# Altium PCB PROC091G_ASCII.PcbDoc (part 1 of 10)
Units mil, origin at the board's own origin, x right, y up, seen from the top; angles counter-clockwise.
Board outline 4538.11 x 994.94 mil, 8 copper layers (Top Layer, GND1, Sig1, PWR1, PWR2, Sig2, GND2, Bottom Layer), stack 59.155 mil thick; 447 components, 329 nets, 5050 pads, 868 vias.
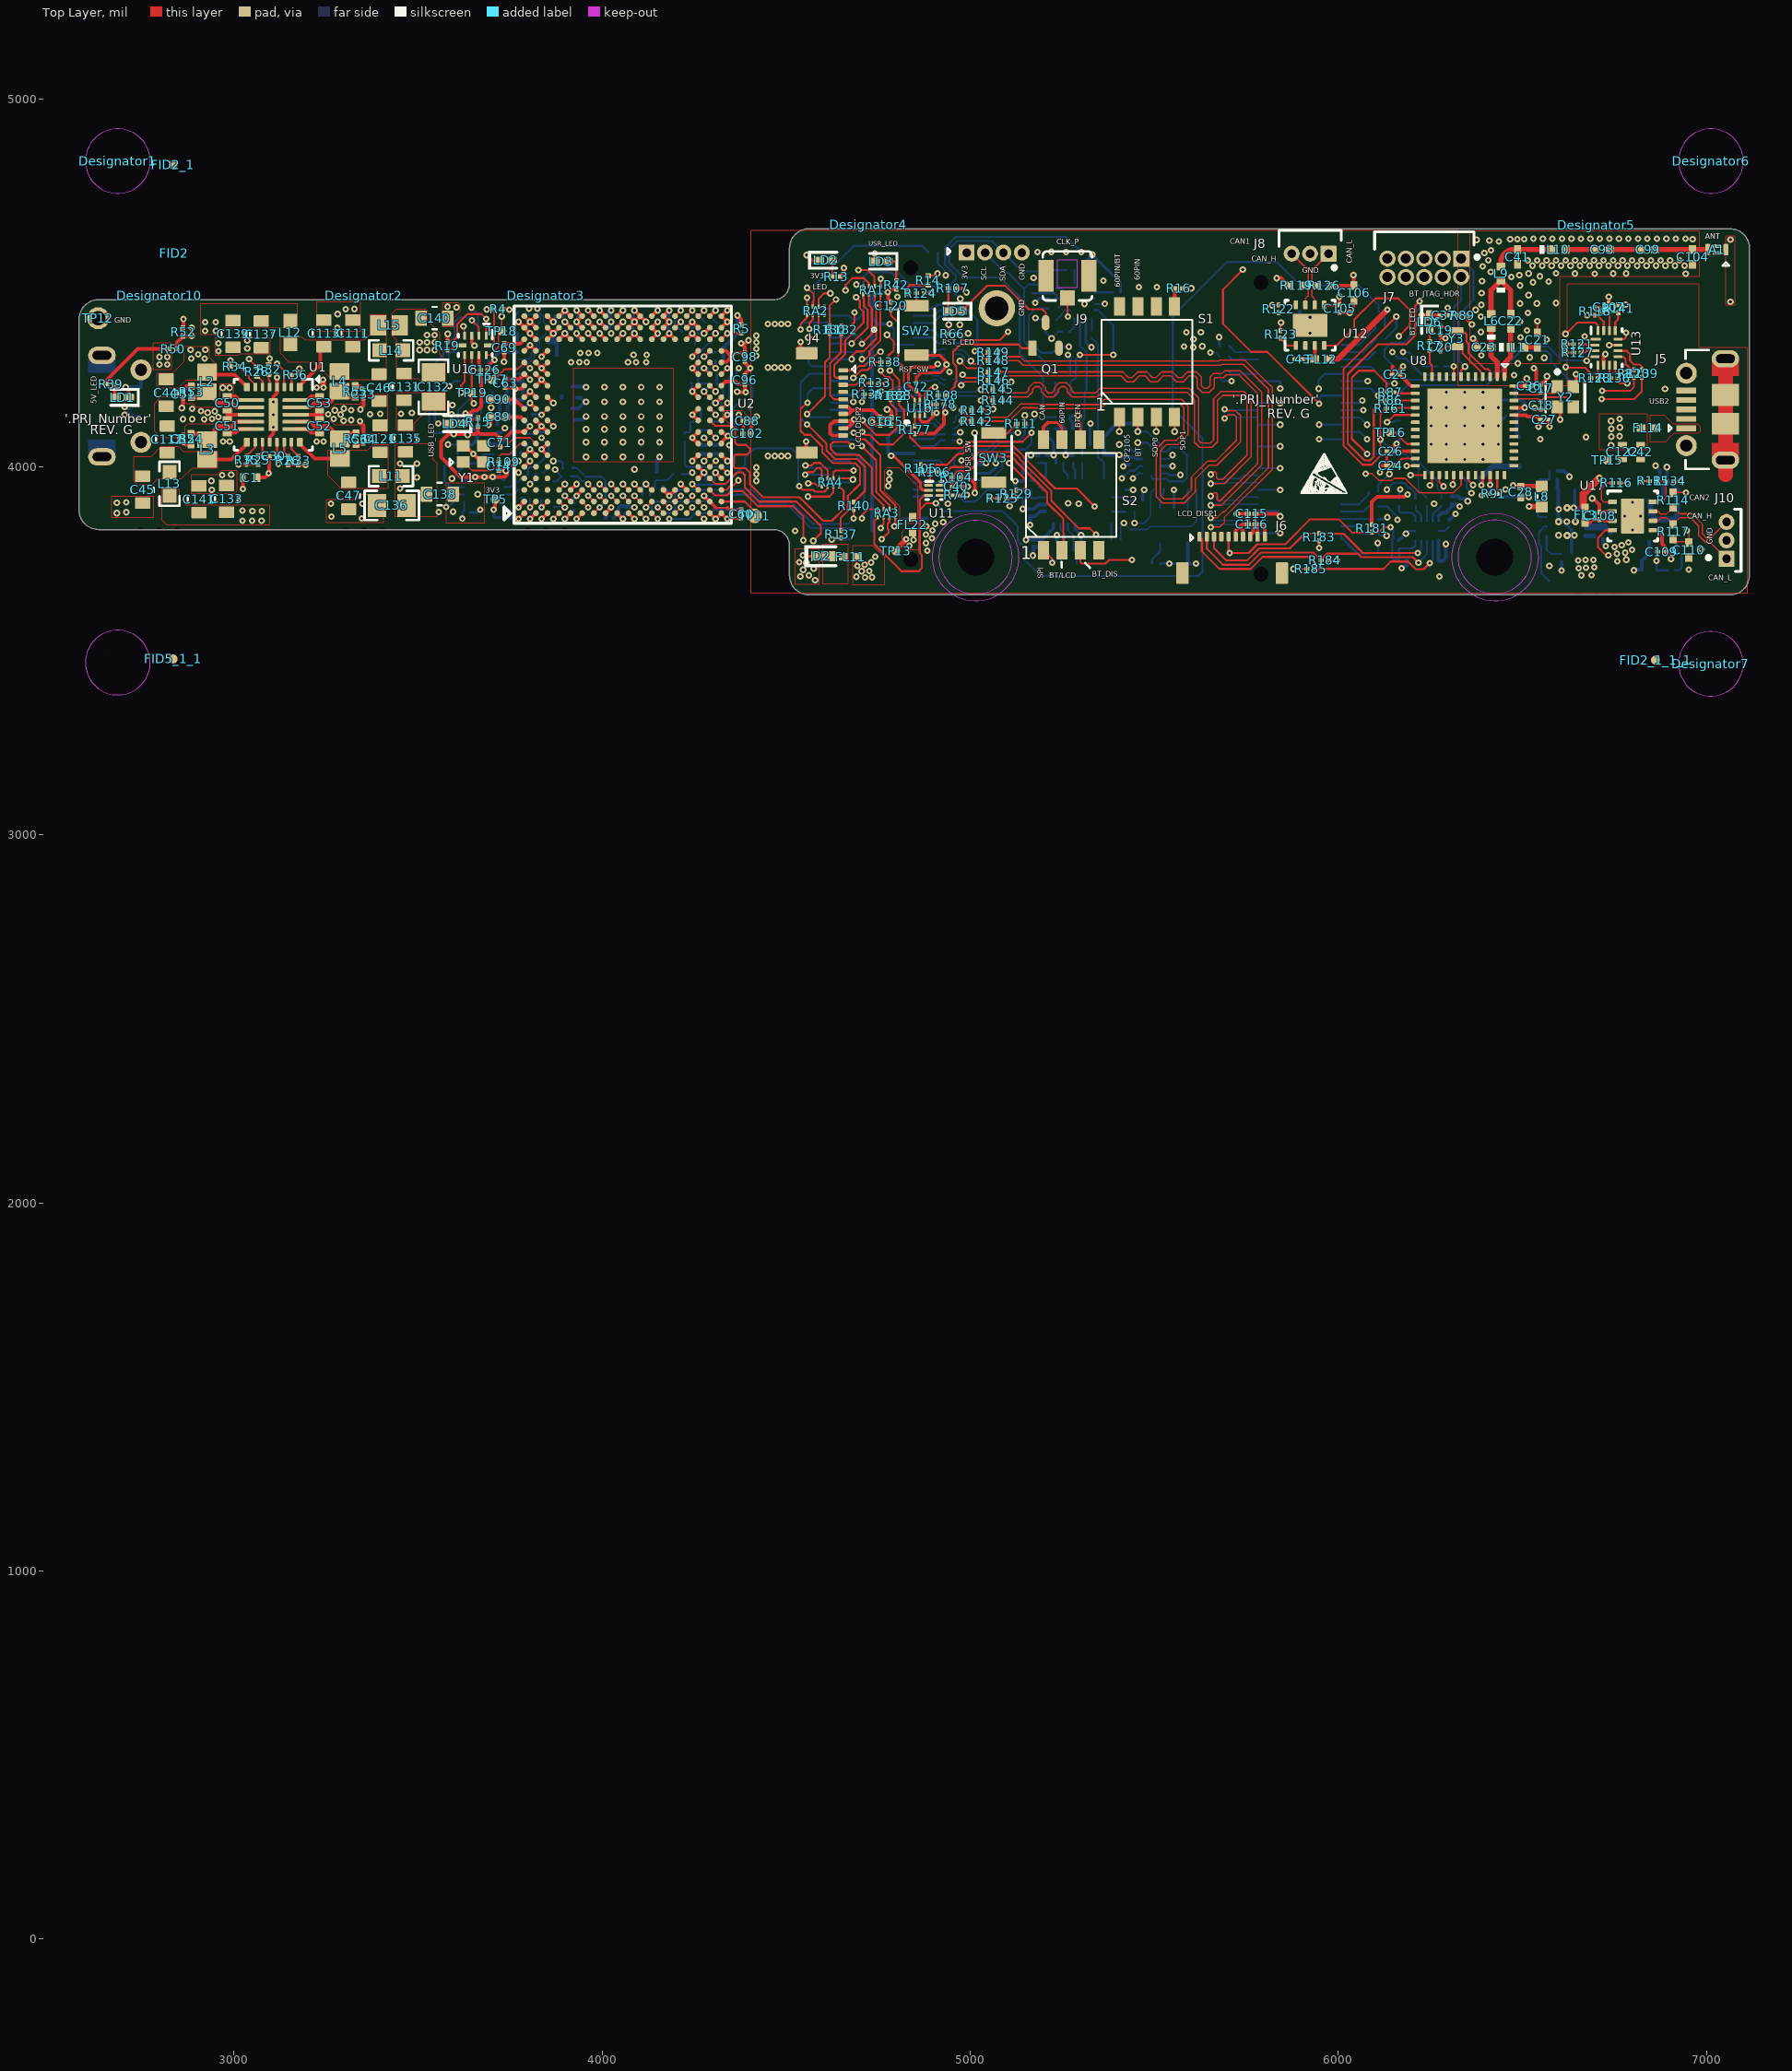
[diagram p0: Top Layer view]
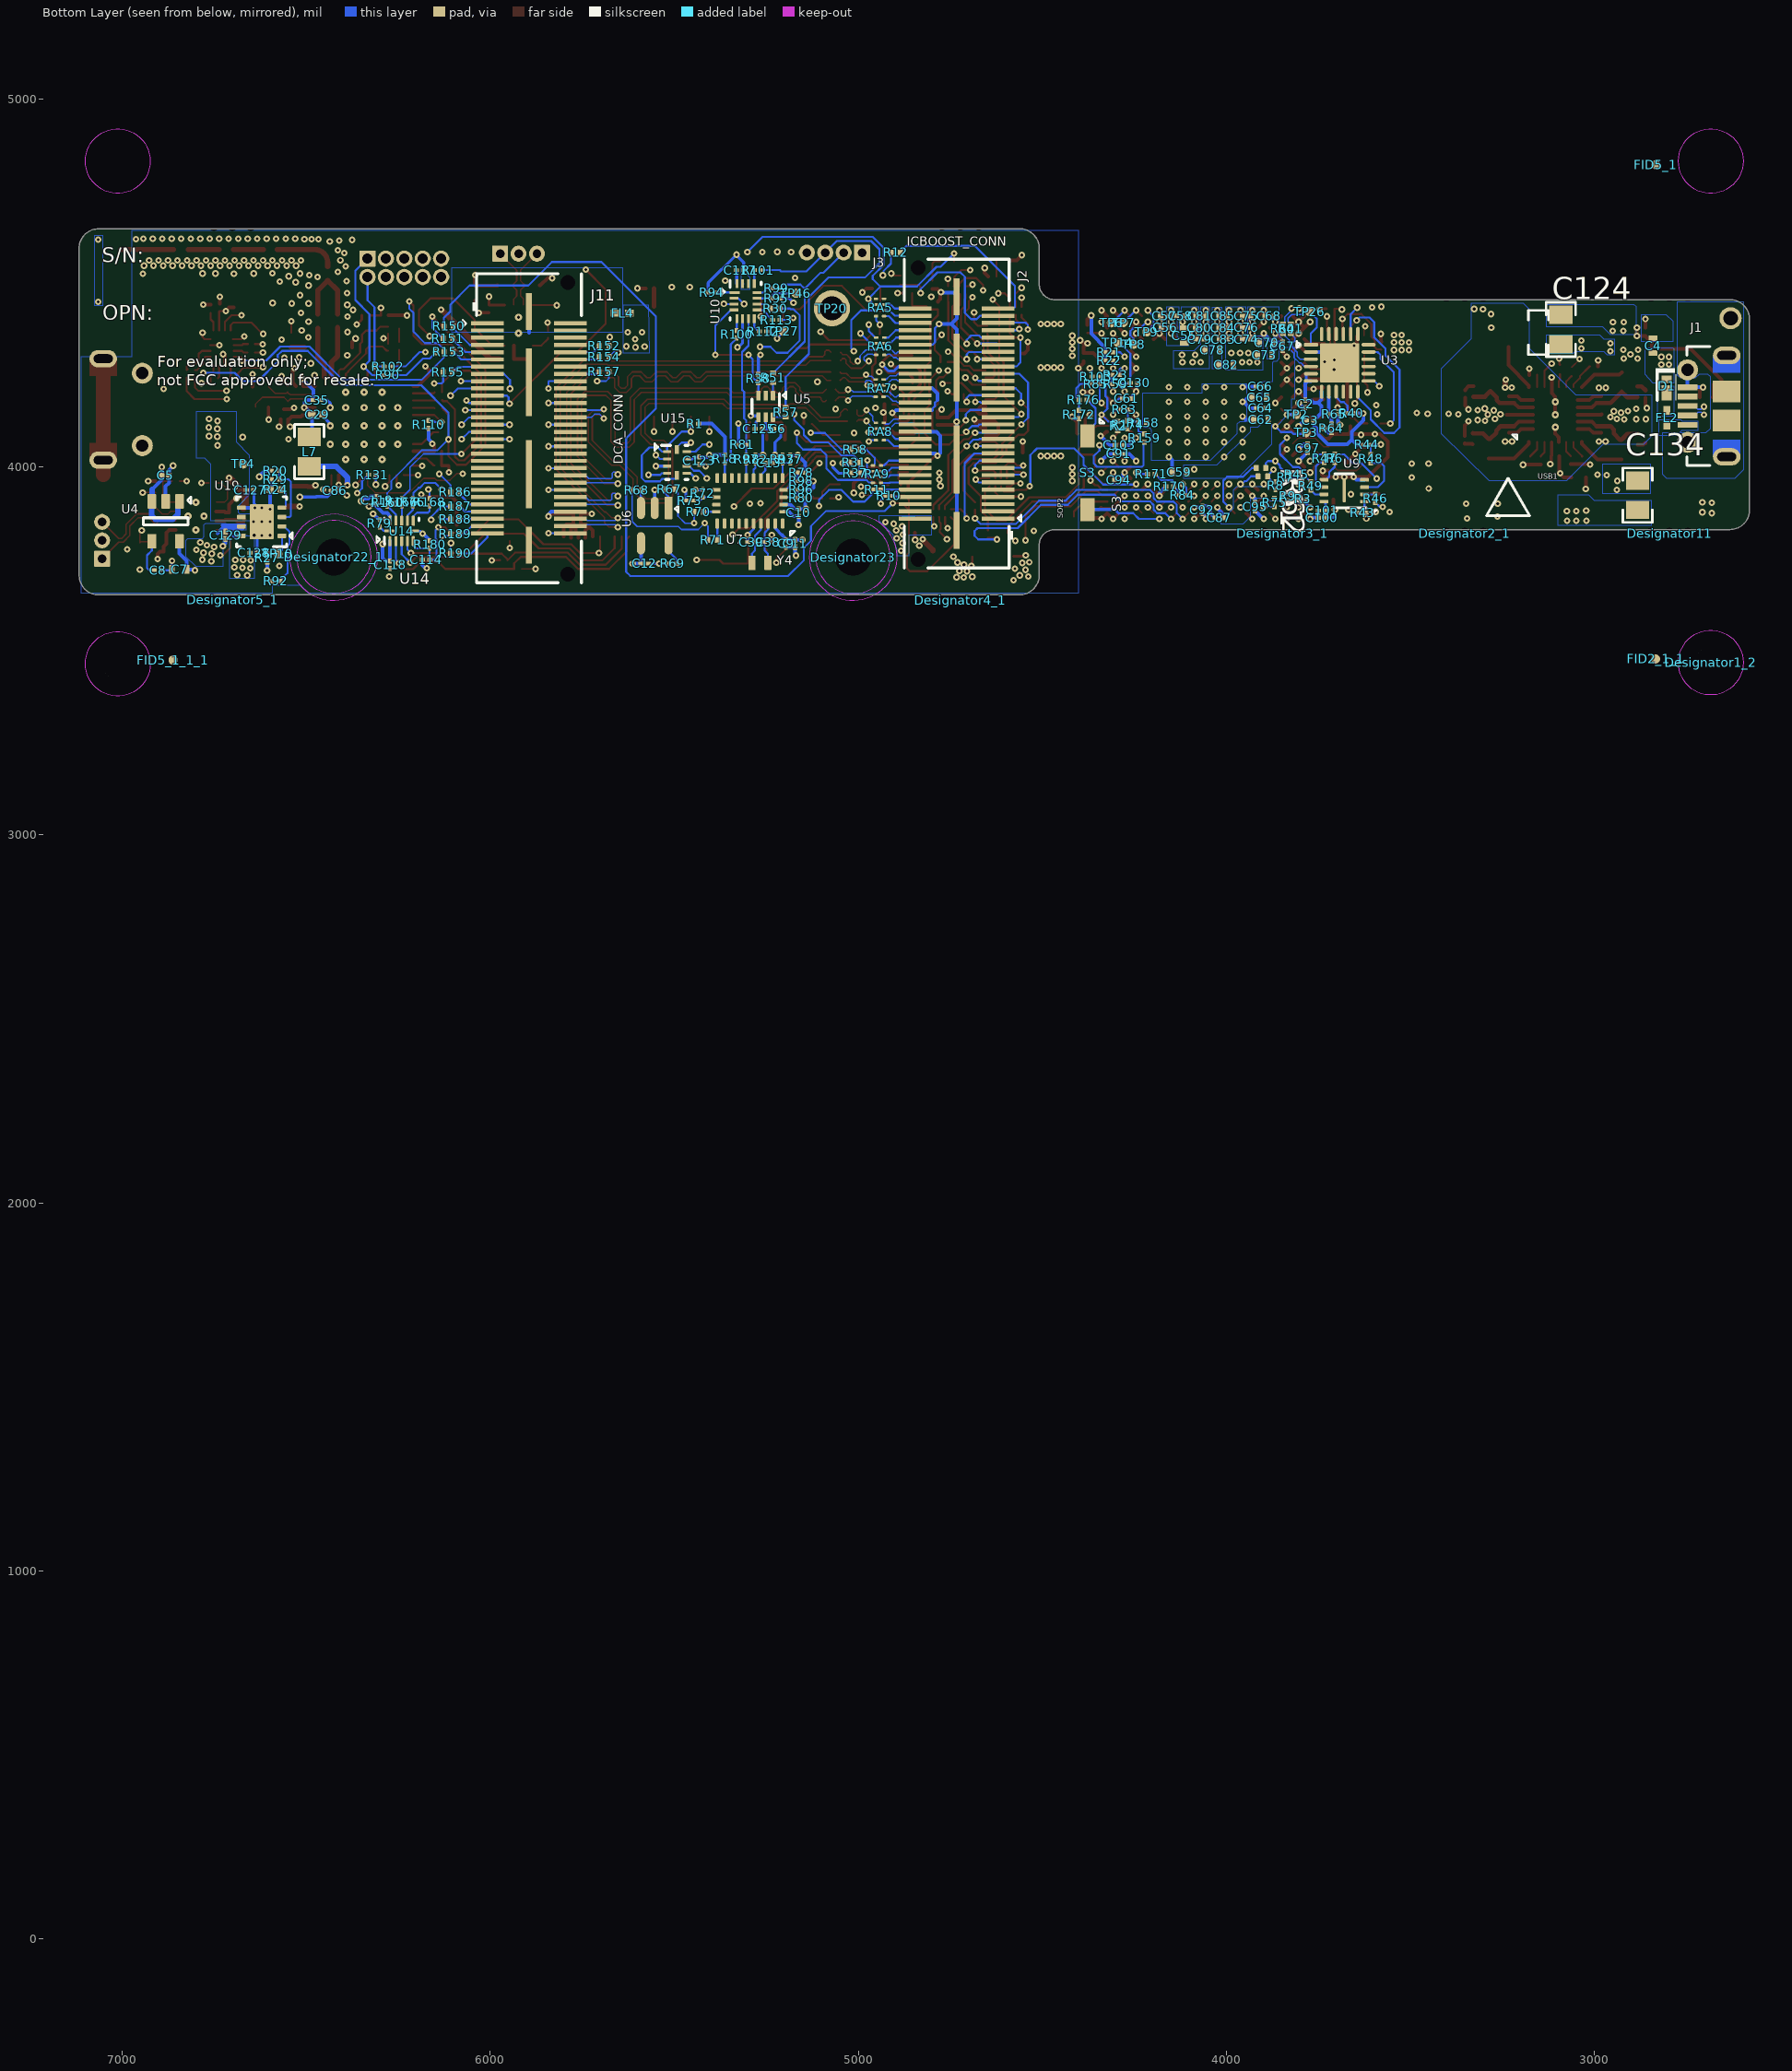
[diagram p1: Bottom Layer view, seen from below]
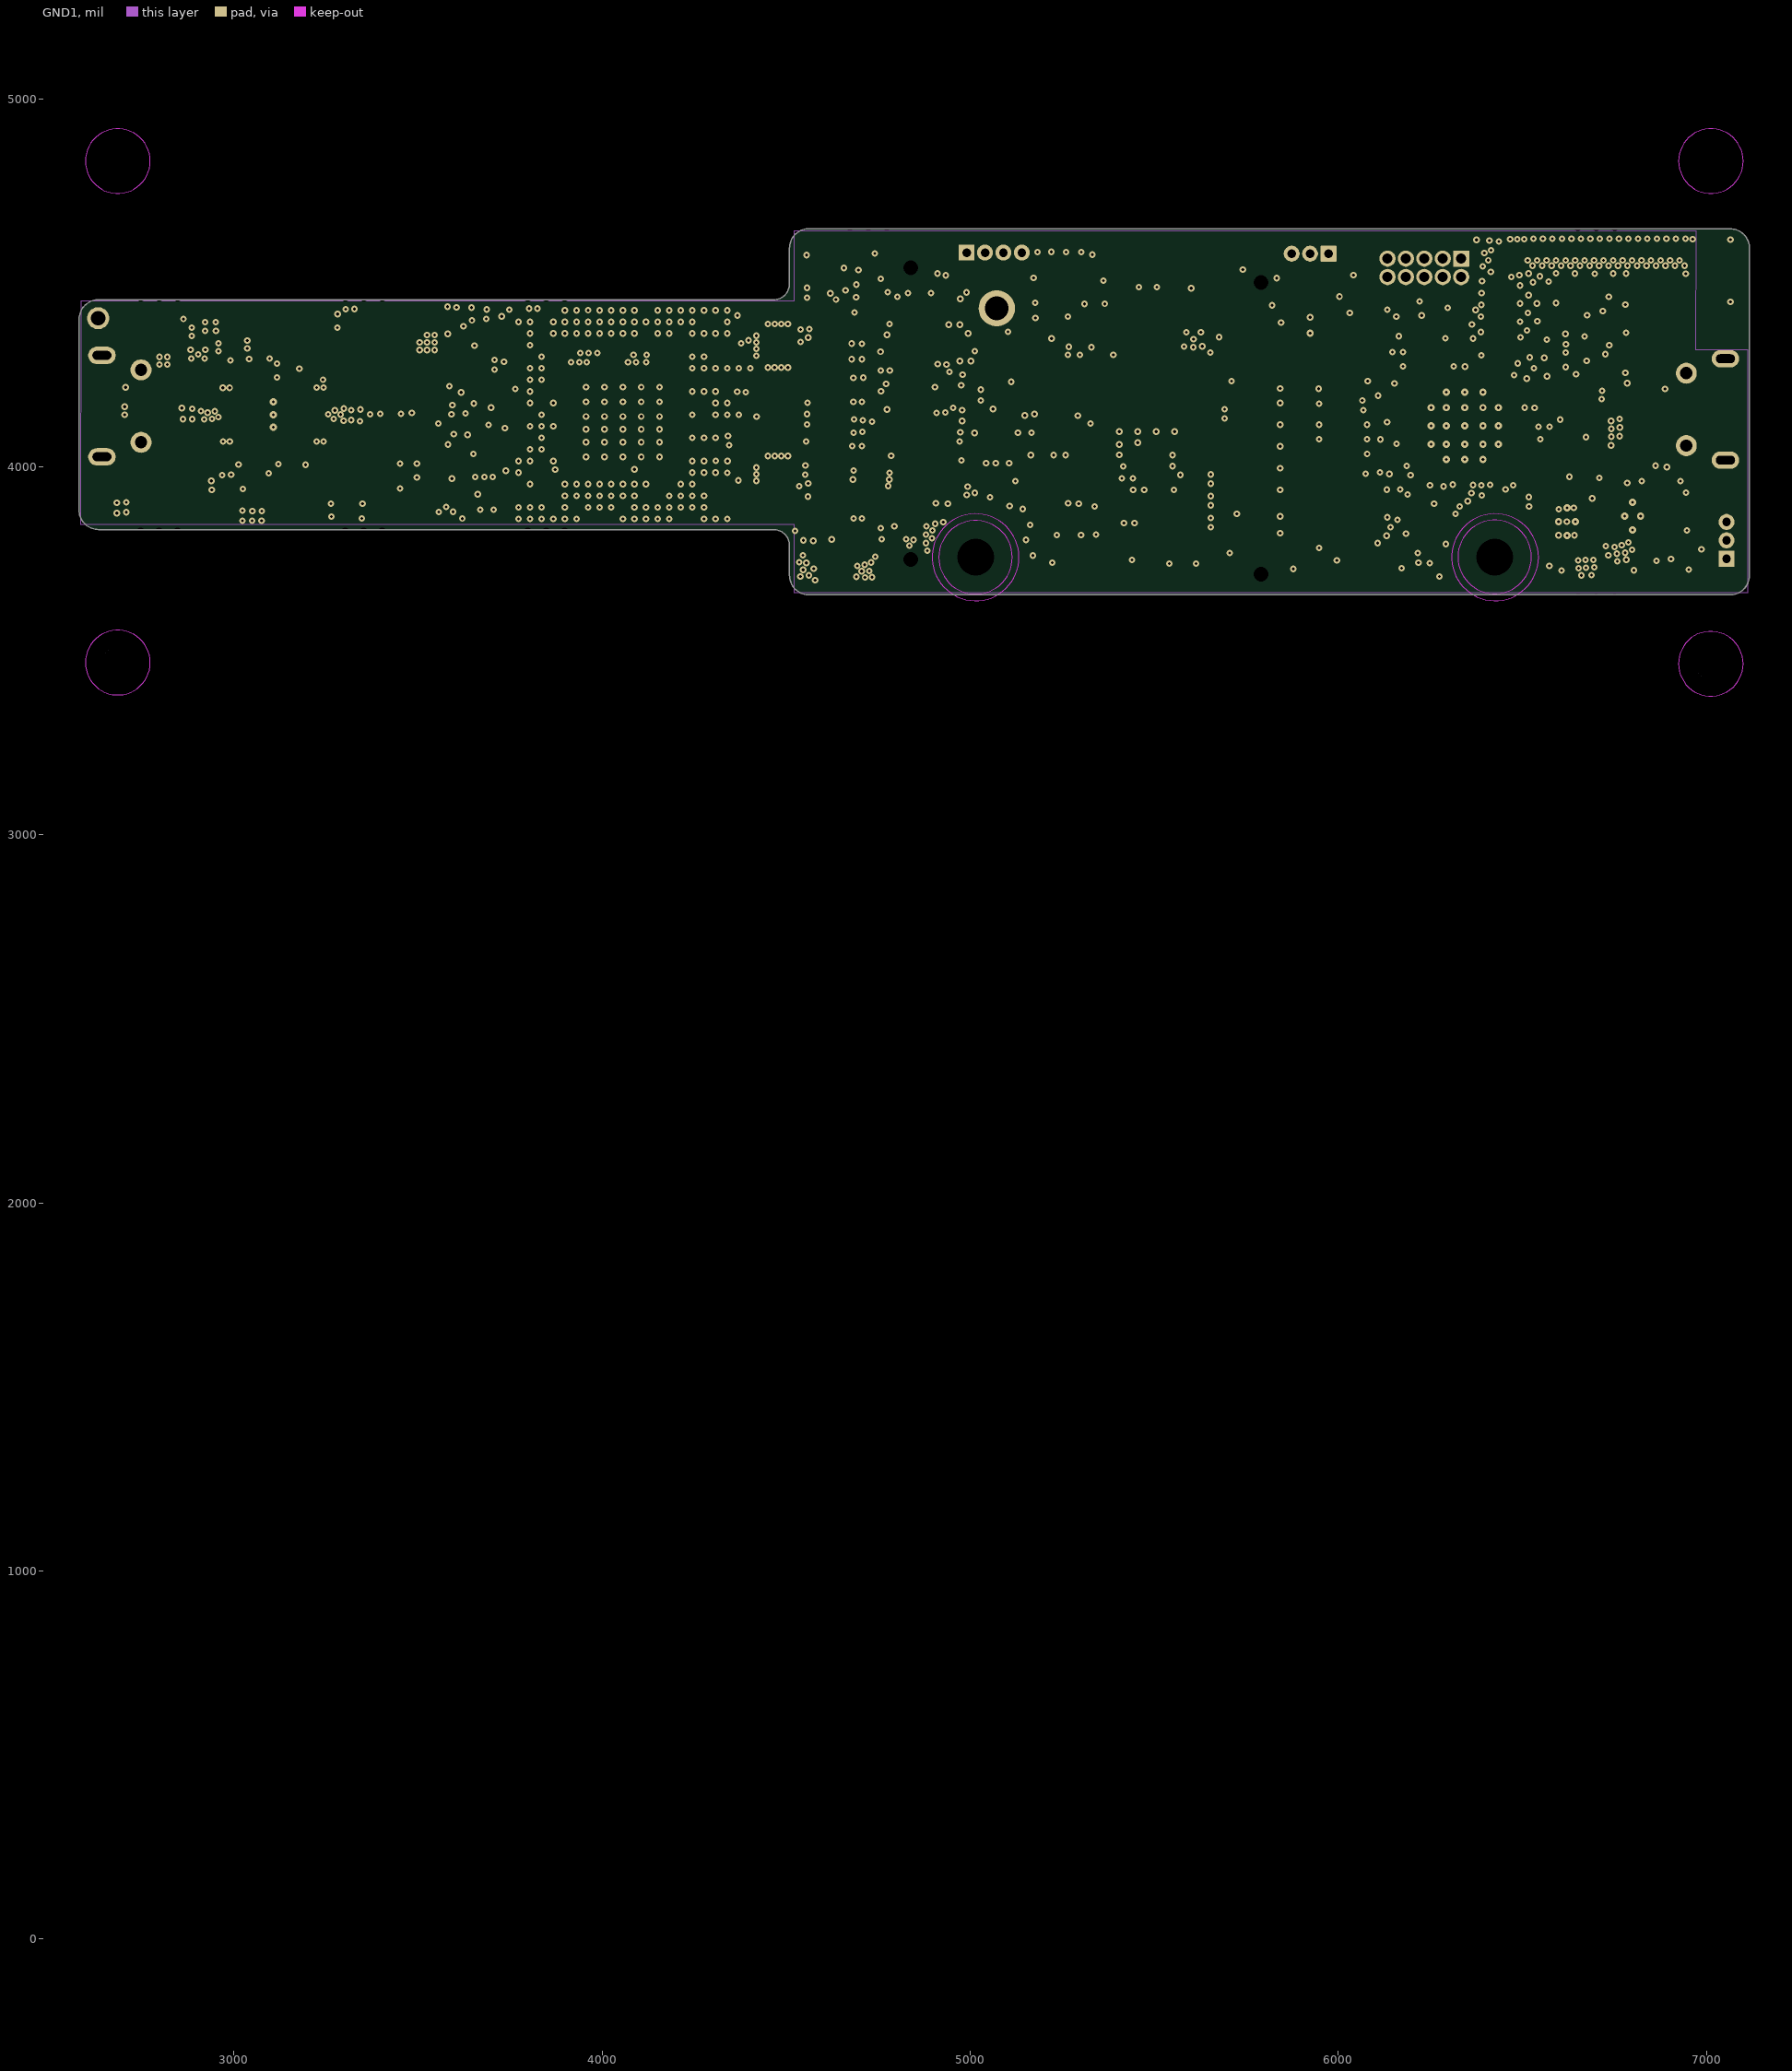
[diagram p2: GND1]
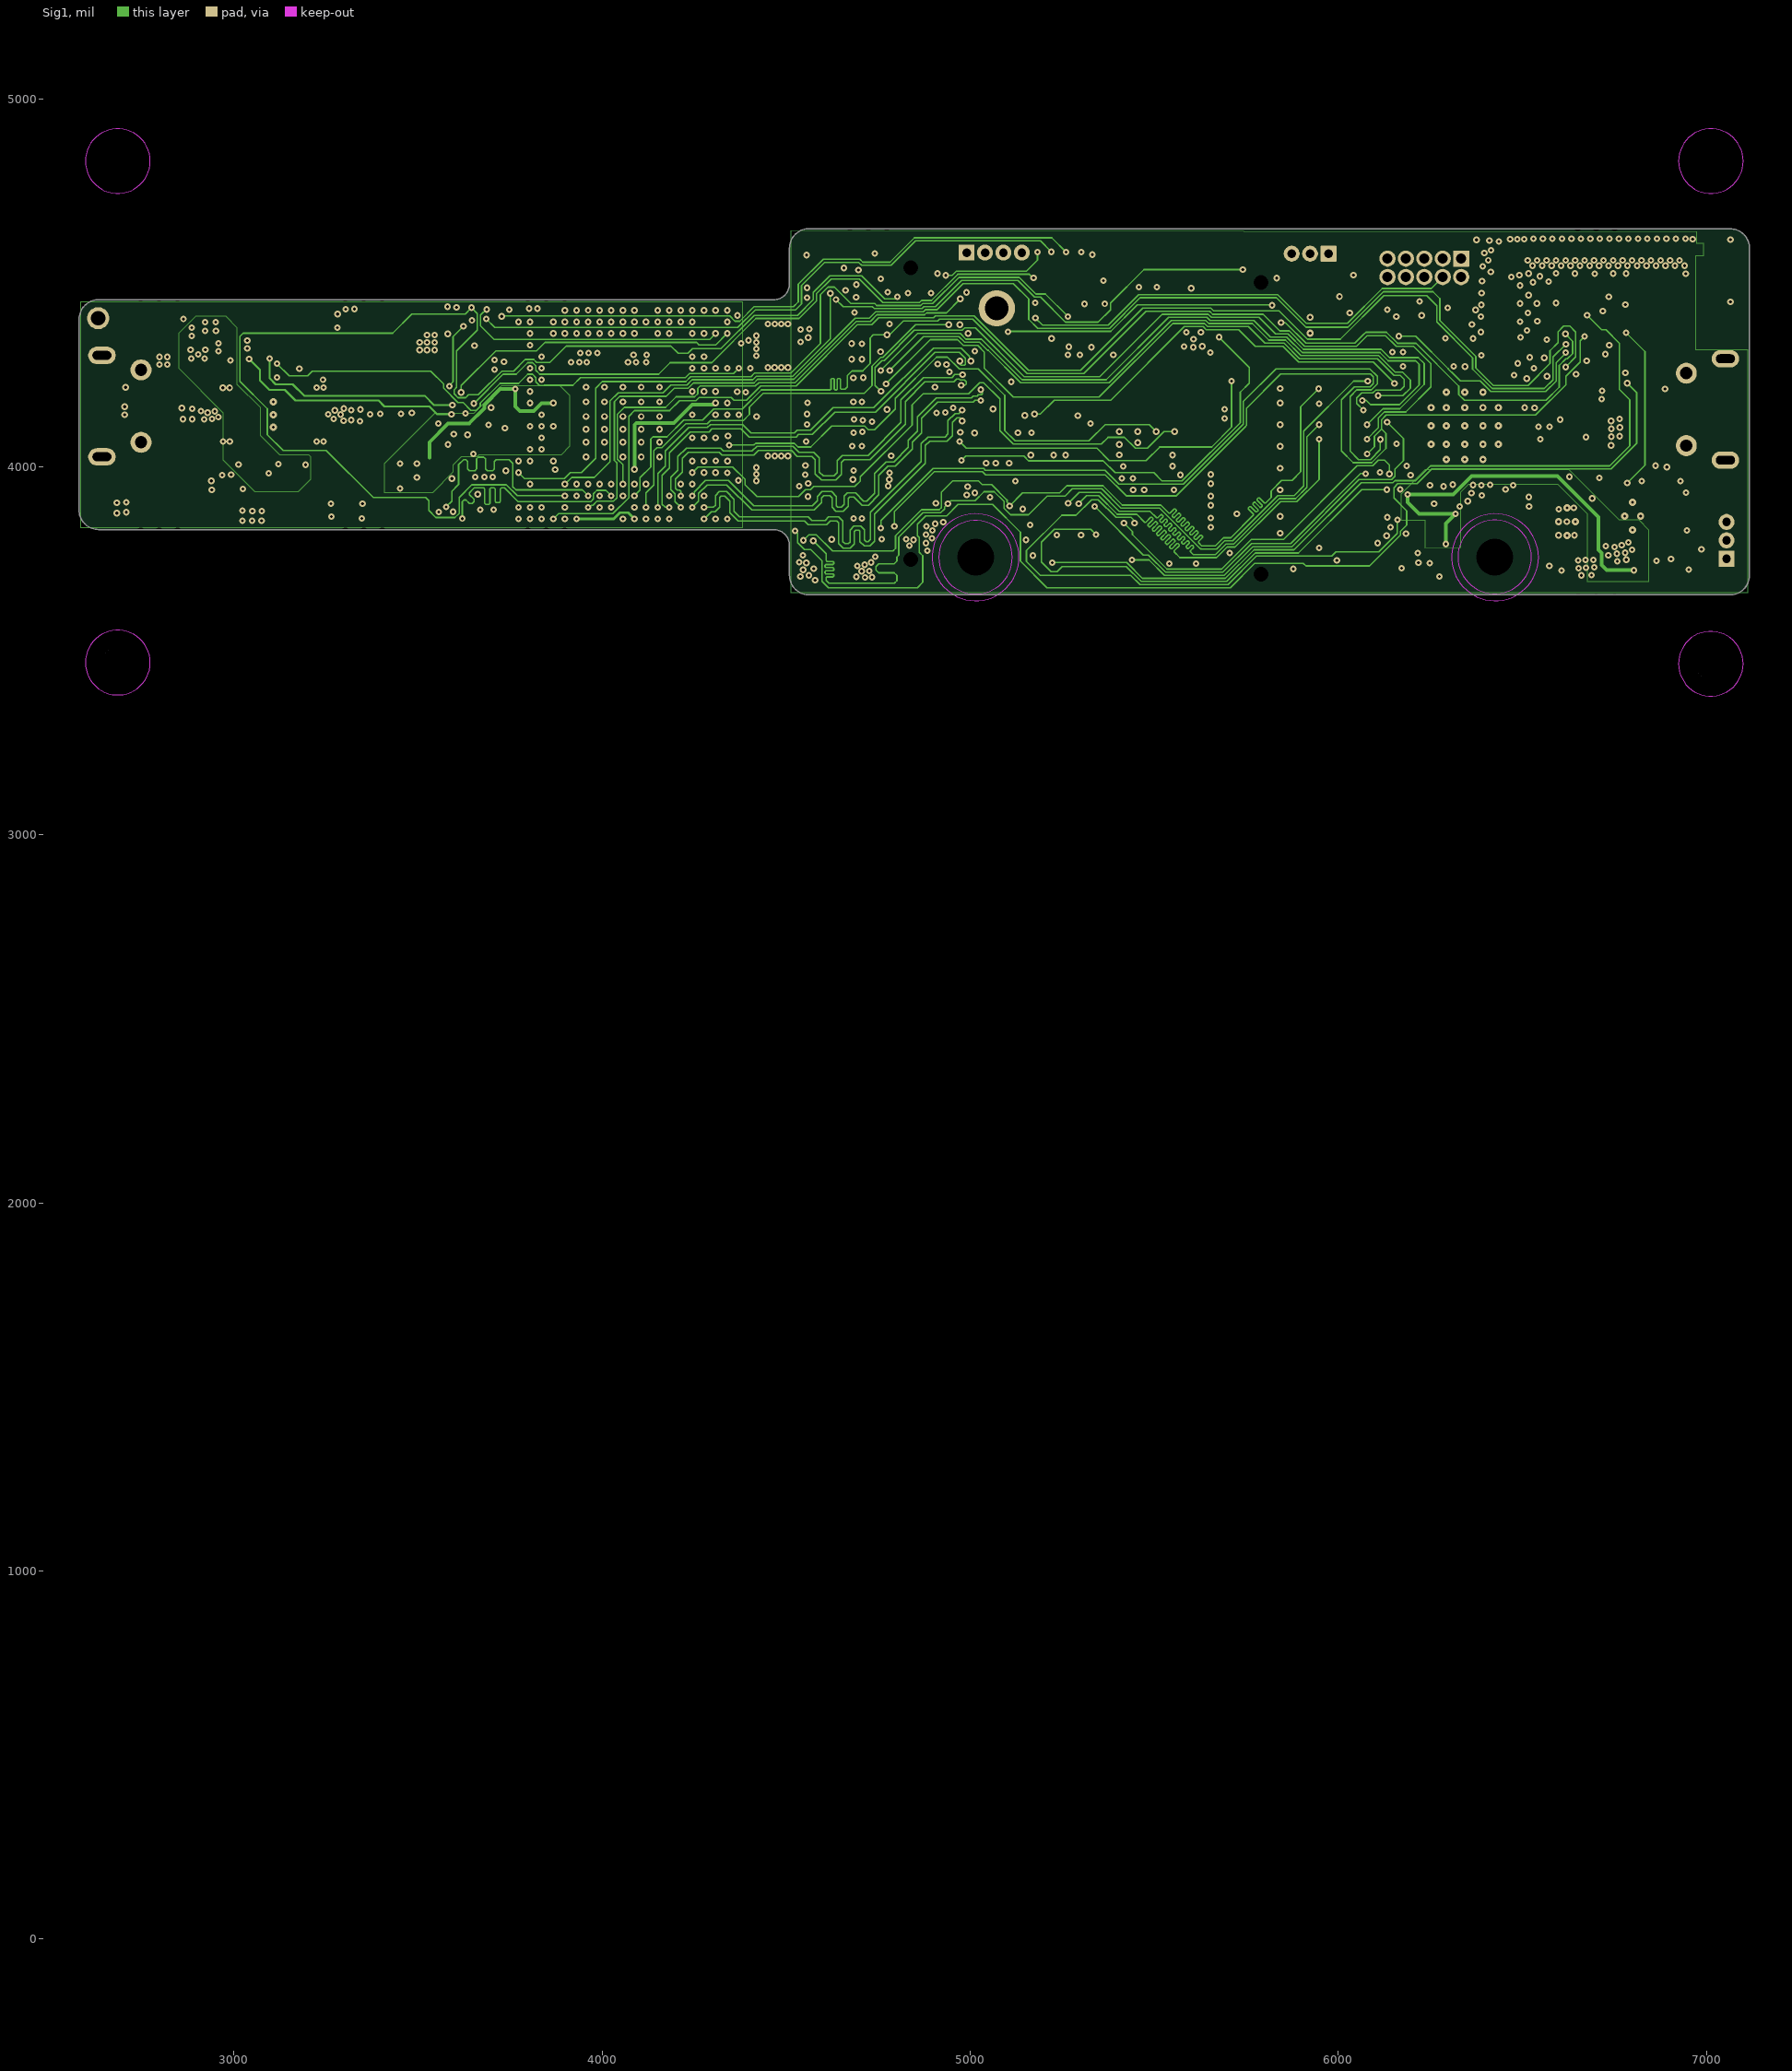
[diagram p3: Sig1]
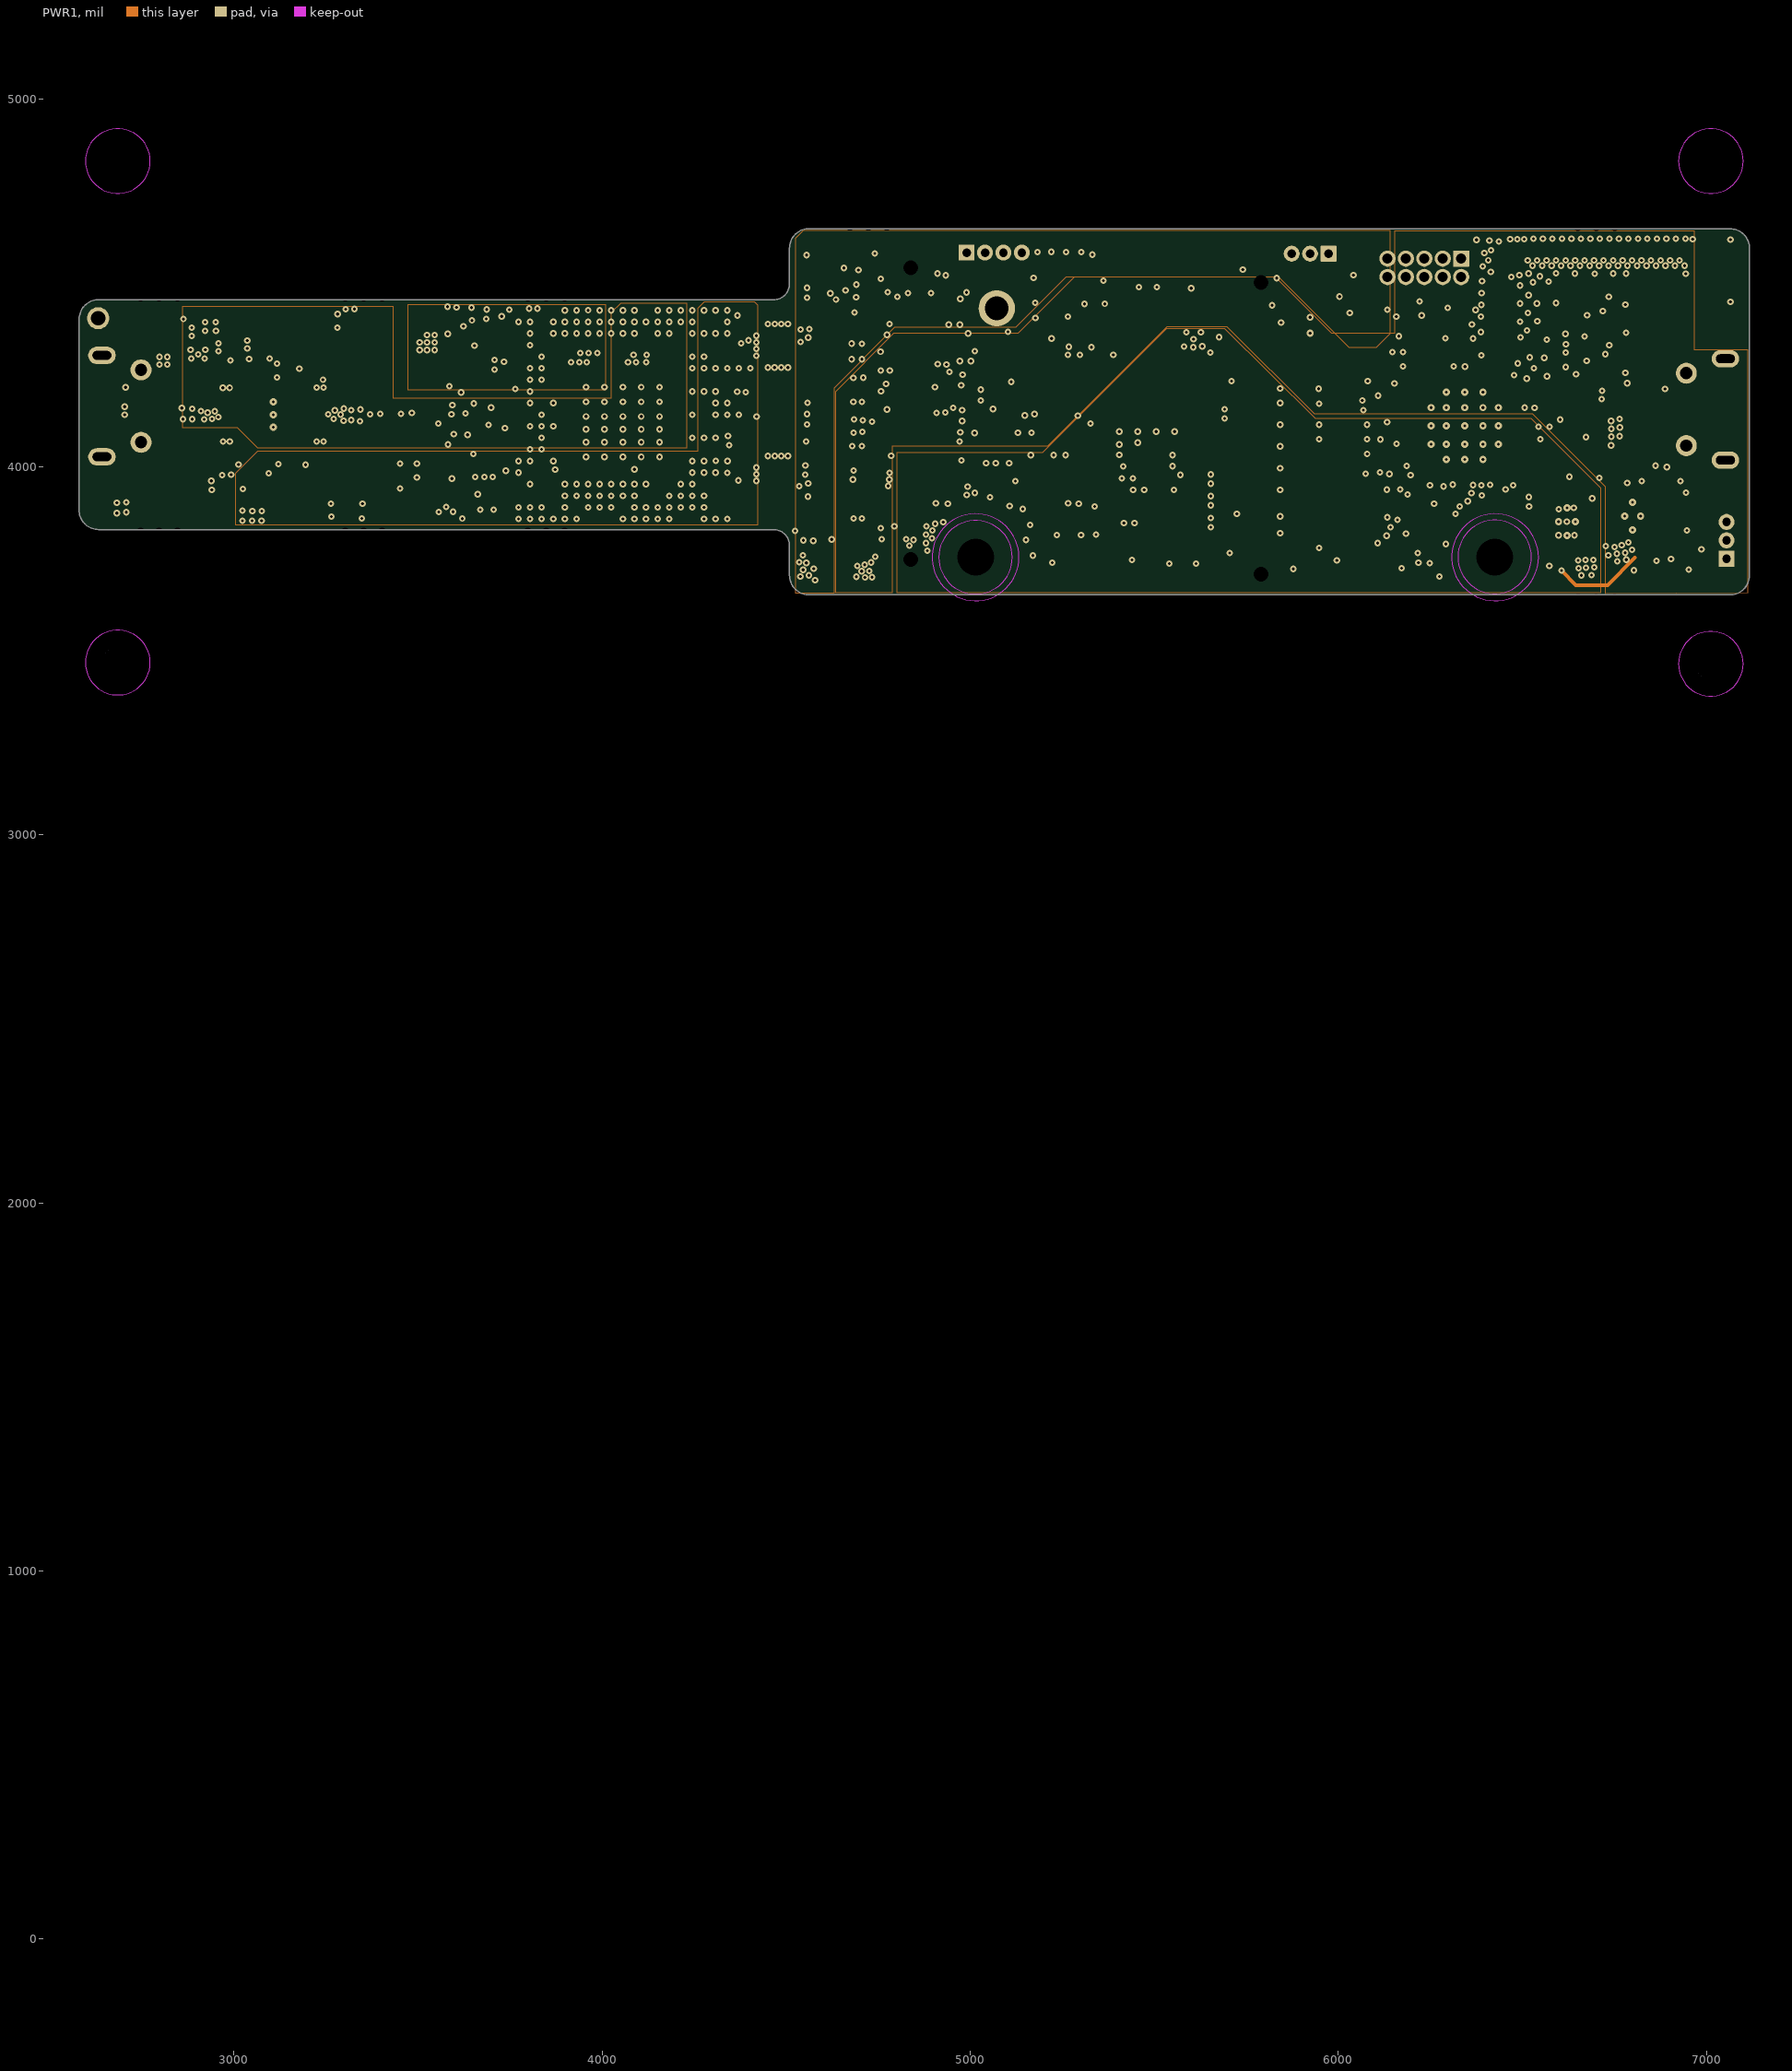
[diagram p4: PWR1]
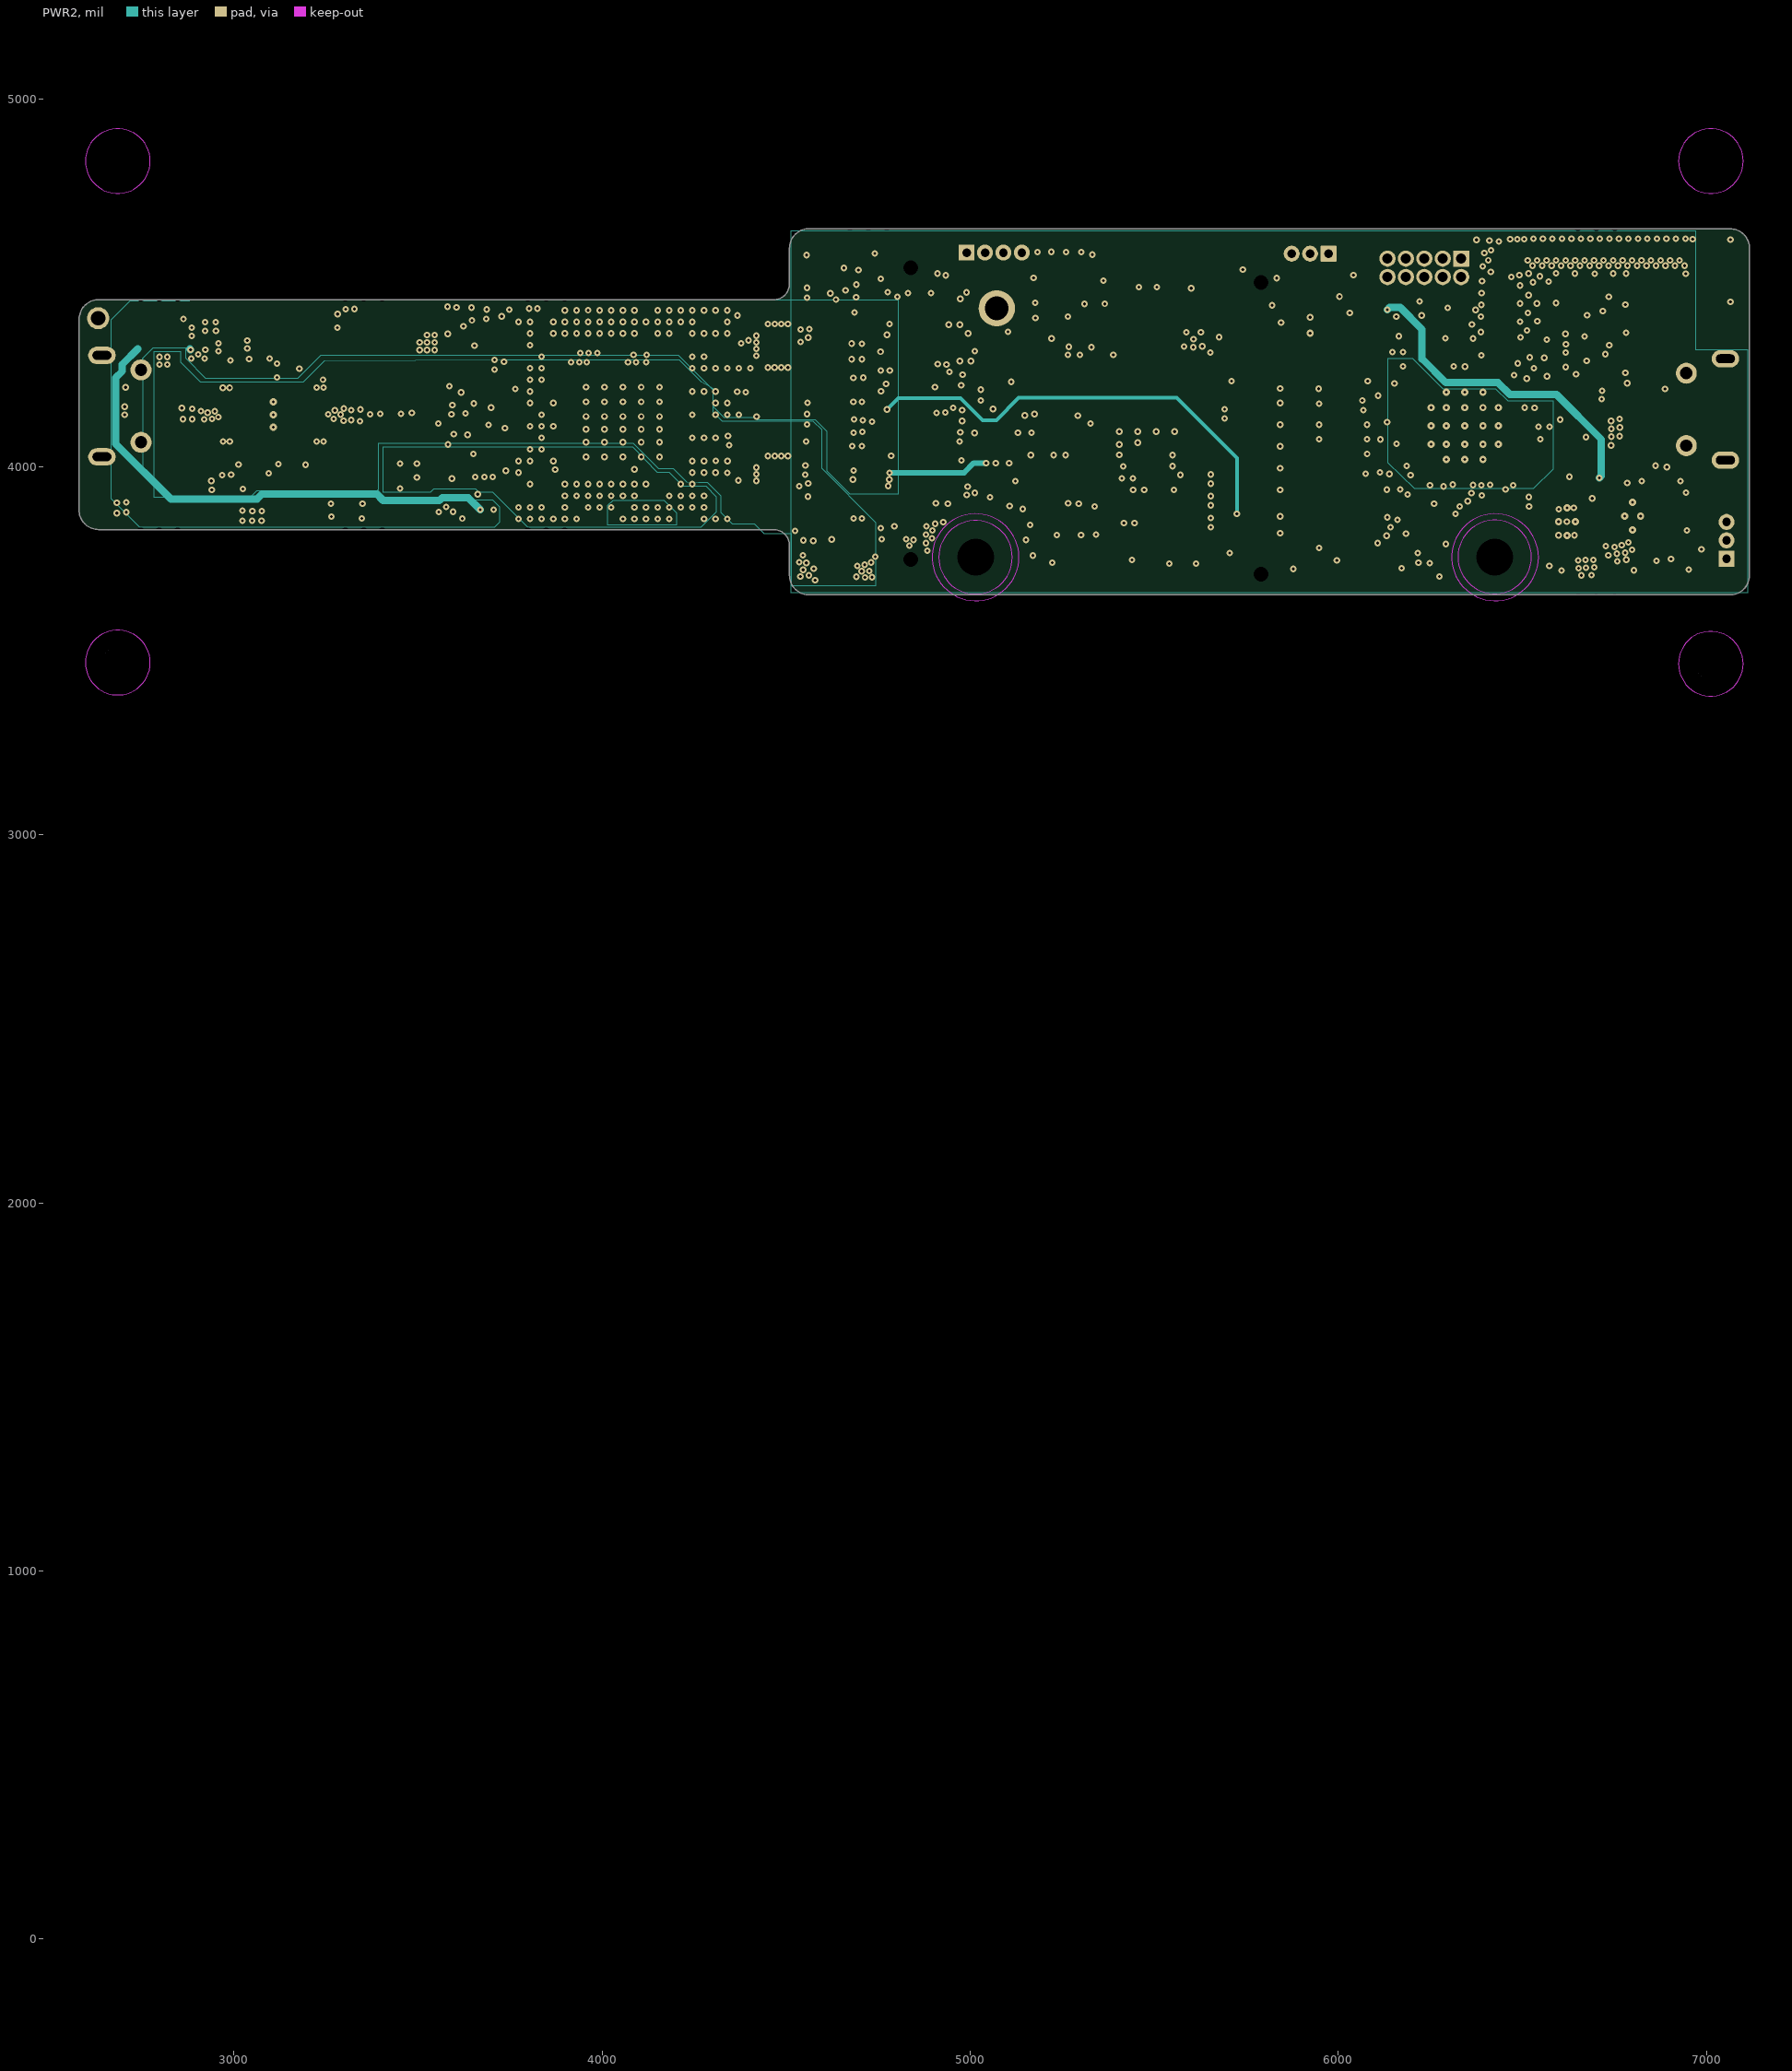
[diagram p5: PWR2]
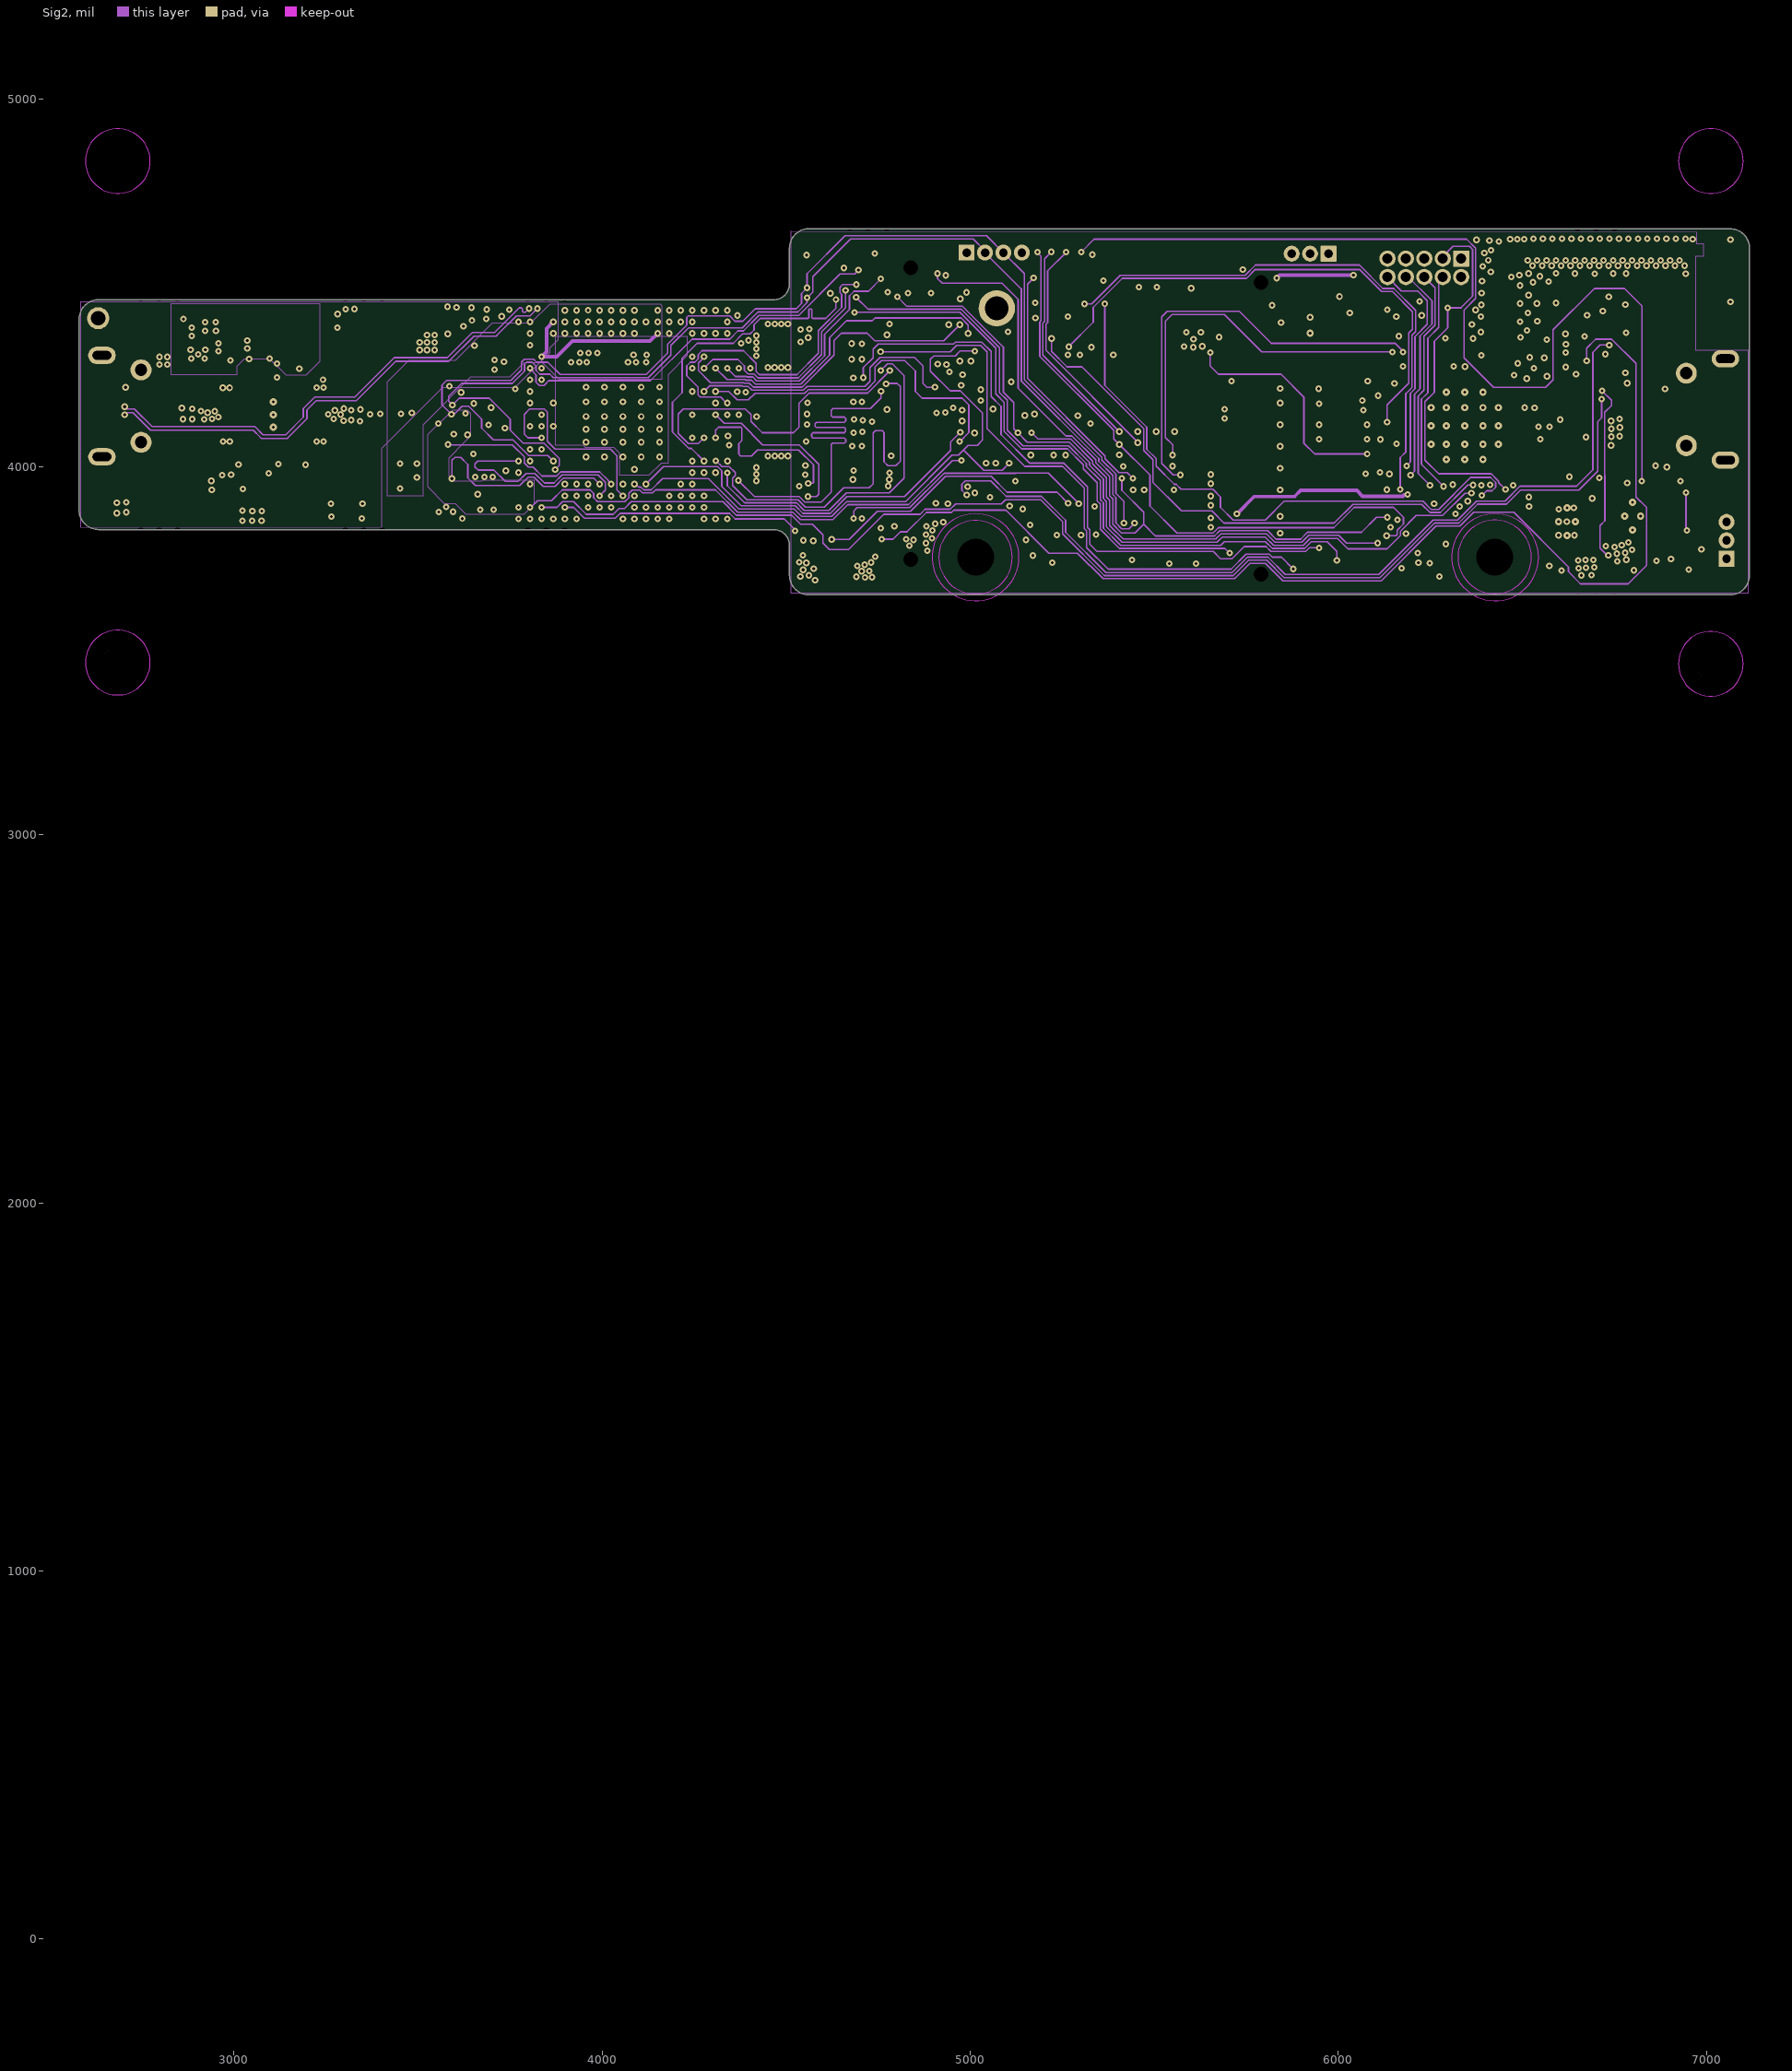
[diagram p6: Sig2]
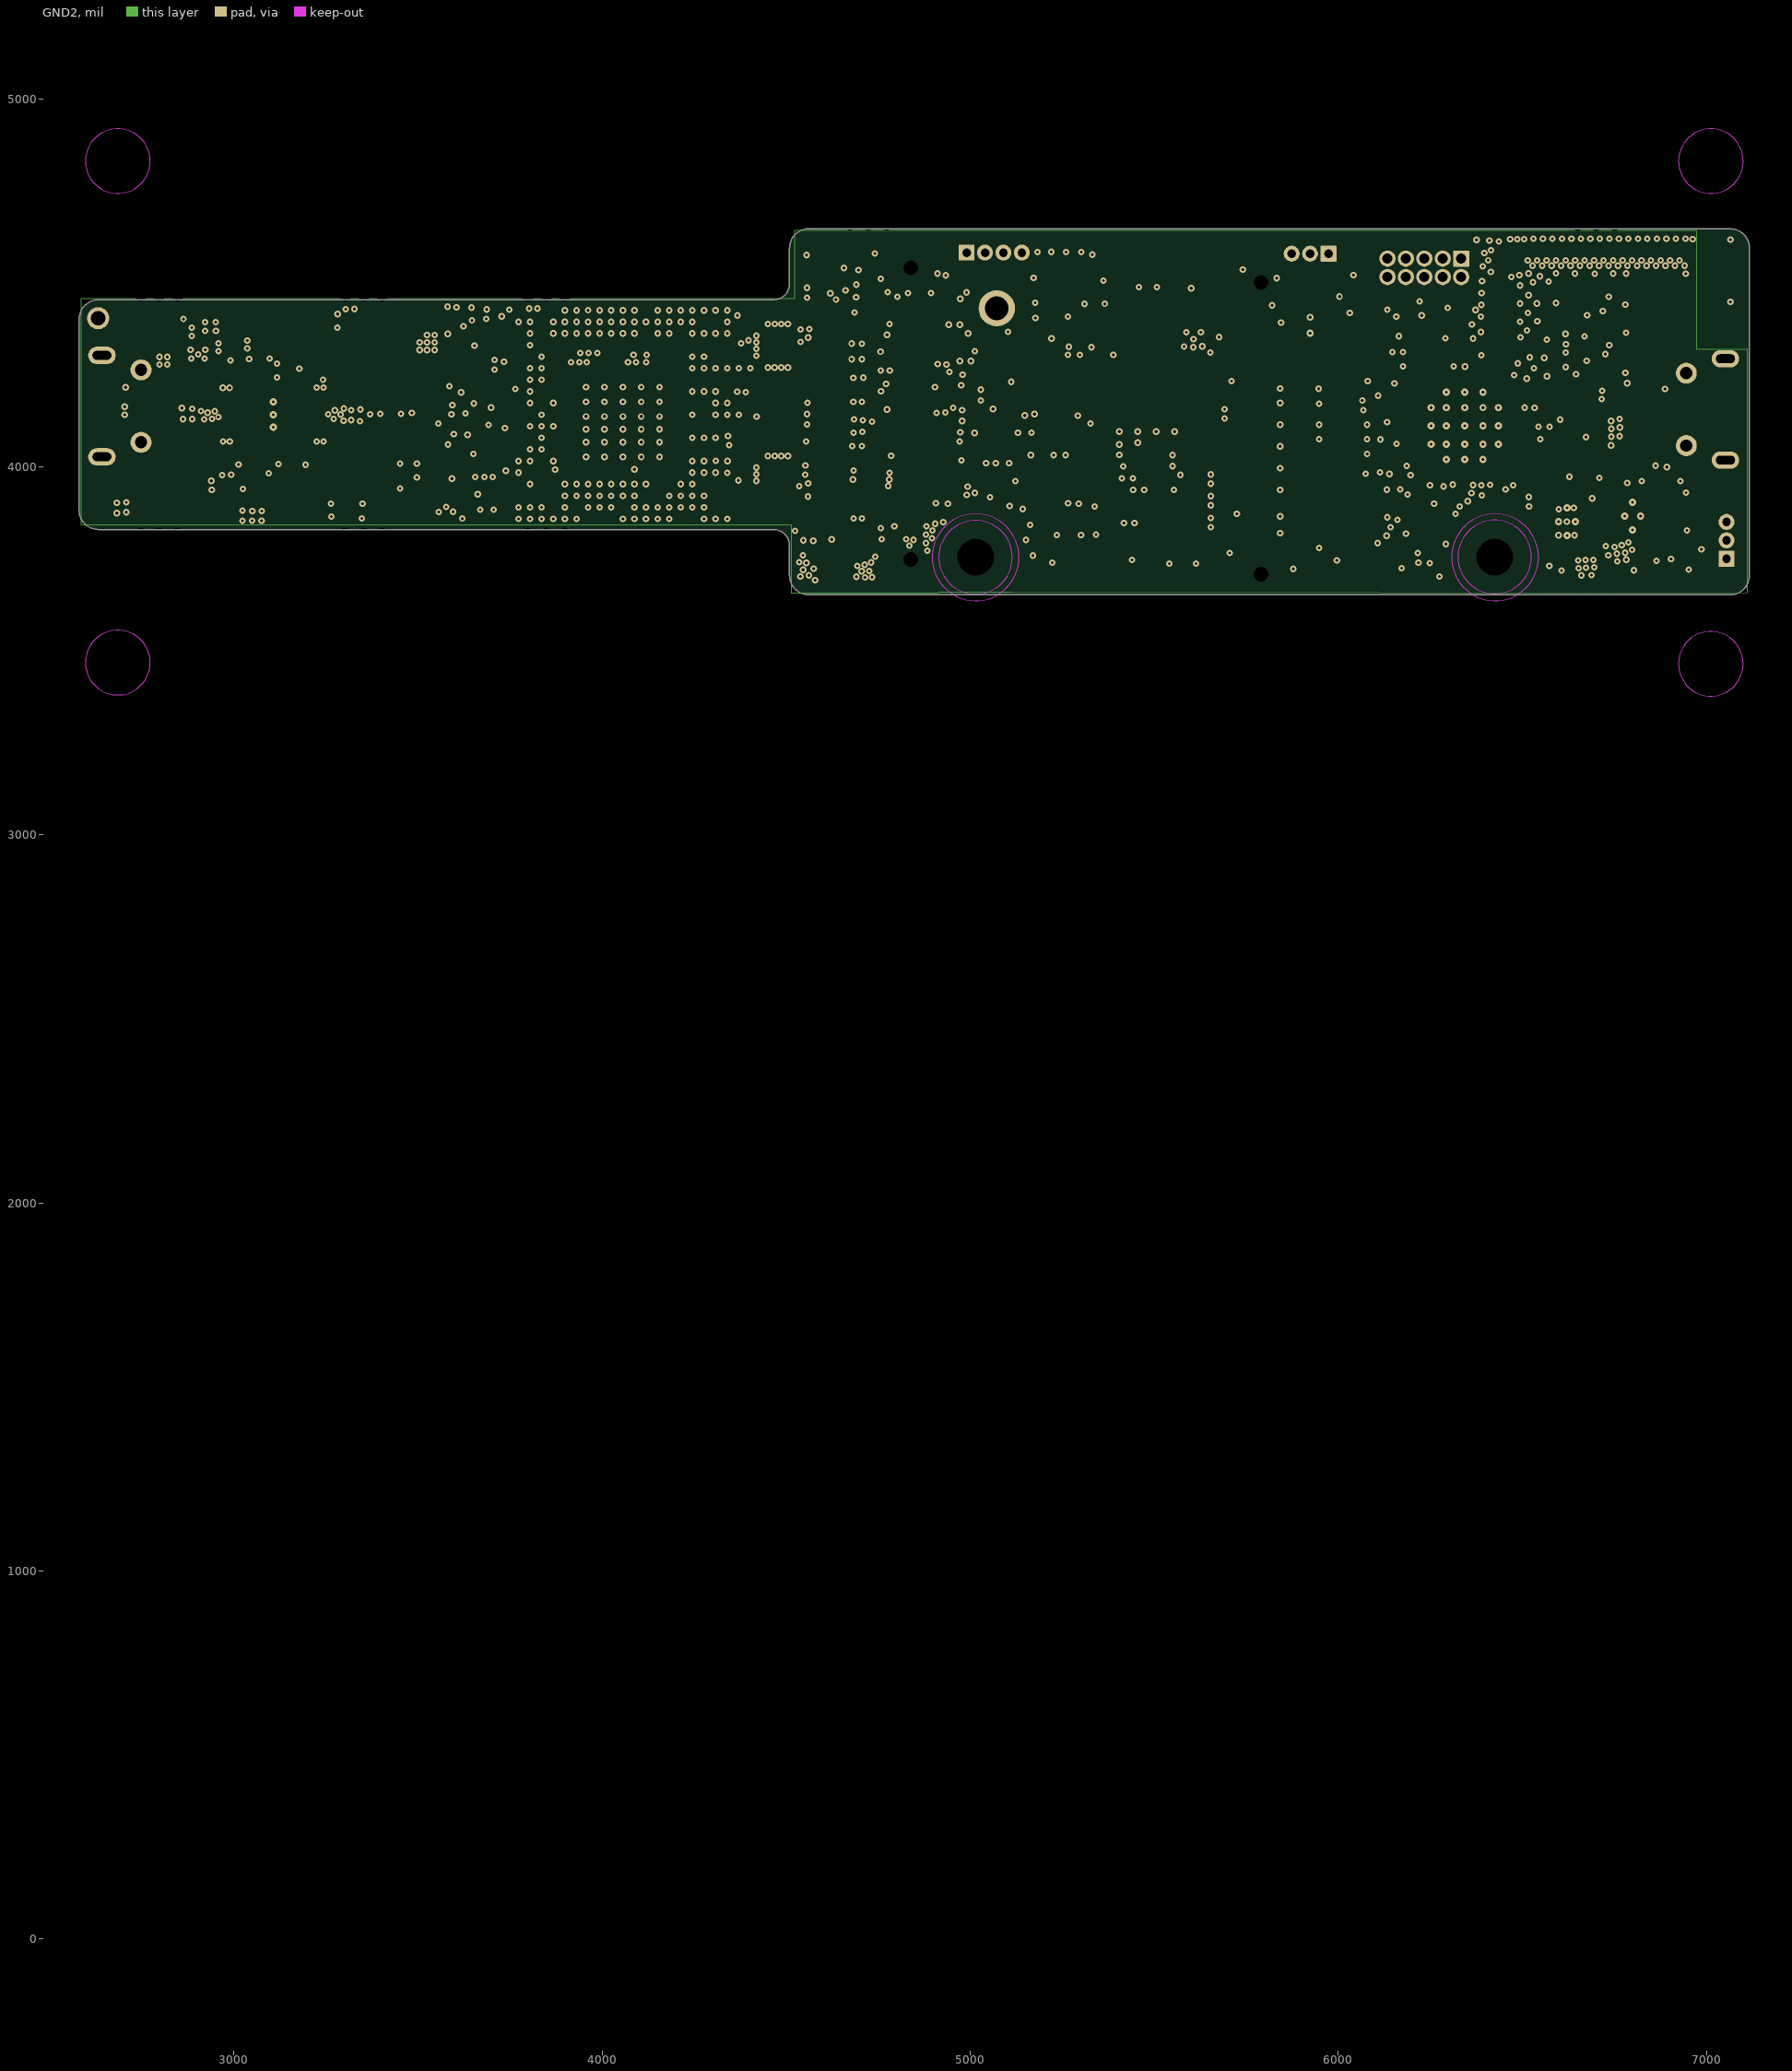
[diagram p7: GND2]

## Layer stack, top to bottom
Top Solder: solder mask 2, Solder Resist, Dk 4.4
Top Layer: signal copper 1.85
Dielectric1: core 1.462, FR-4 High Tg, Dk 3.79
Dielectric 2: dielectric 2.224, Dk 3.86
GND1: signal copper 2.638
Dielectric3: dielectric 4, FR-4 High Tg, Dk 4.4
Sig1: signal copper 1.26
Dielectric4: dielectric 3.162, FR-4 High Tg, Dk 4.13
Dielectric 5: dielectric 3.162, Dk 4.13
Dielectric 6: dielectric 3.162, Dk 4.13
PWR1: signal copper 2.638
Dielectric7: dielectric 8, FR-4 High Tg, Dk 4.41
PWR2: signal copper 2.638
Dielectric8: dielectric 3.175, FR-4 High Tg, Dk 4.13
Dielectric 9: dielectric 3.175, Dk 4.13
Dielectric 10: dielectric 3.175, Dk 4.13
Sig2: signal copper 1.26
Dielectric11: dielectric 4, FR-4 High Tg, Dk 4.4
GND2: signal copper 2.638
Dielectric12: dielectric 2.224, FR-4 High Tg, Dk 3.86
Dielectric 13: dielectric 1.462, Dk 3.79
Bottom Layer: signal copper 1.85
Bottom Solder: solder mask 2, Solder Resist, Dk 4.4

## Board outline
2632.27,3829.45 2632.34,3829.45 4466.14,3829.45 cw(c4466.14,3786.46) 4509.12,3786.46 4509.12,3705.09 ccw(c4562.14,3705.09) 4562.14,3652.08 ccw(c4562.14,3657.09) 4562.83,3652.13 7062.33,3652.13 ccw(c7064.08,3656.83) 7064.08,3651.81 ccw(c7064.08,3704.83) 7117.07,3703.16 ccw(c7112.34,3704.83) 7117.35,3704.83 7117.35,4593.25 ccw(c7112.34,4593.47) 7117.36,4593.47 ccw(c7064.34,4593.47) 7064.34,4646.49 ccw(c7064.34,4641.47) 7063.39,4646.4 4562.79,4646.71 ccw(c4562.15,4641.74) 4562.15,4646.75 ccw(c4562.15,4593.74) 4509.14,4593.74 4509.14,4496.76 4509.13,4496.76 cw(c4514.15,4496.76) 4509.14,4496.84 4509.13,4496.76 cw(c4466.15,4496.76) 4466.15,4453.77 2634.33,4453.77 ccw(c2632.58,4449.07) 2632.58,4454.09 ccw(c2632.58,4401.07) 2579.56,4401.07 ccw(c2584.58,4401.07) 2579.57,4400.91 ccw(c2584.58,4400.76) 2579.56,4400.76 2579.56,3884.21 ccw(c2584.27,3882.46) 2579.25,3882.46 ccw(c2632.27,3882.46)

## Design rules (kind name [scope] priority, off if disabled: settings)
AcuteAngle [All] p0: scope1count=1 scope1_0_kind=Board scope1_0_value=Board scope2count=1 scope2_0_kind=Board scope2_0_value=Board commentlength=0 minimum=4.50000000000000E+0001
AcuteAngle [All] p1: minimum=4.50000000000000E+0001 checktracksonly=TRUE
AssemblyTestPointUsage [All] p0: scope1count=1 scope1_0_kind=Board scope1_0_value=Board scope2count=1 scope2_0_kind=Board scope2_0_value=Board commentlength=0
AssemblyTestPointUsage [All] p1: valid=2
AssemblyTestpoint [All] p0: scope1count=1 scope1_0_kind=Board scope1_0_value=Board scope2count=1 scope2_0_kind=Board scope2_0_value=Board commentlength=0
BoardOutlineClearance [All] p0 off: scope1count=1 scope1_0_kind=Board scope1_0_value=Board scope2count=1 scope2_0_kind=Board scope2_0_value=Board commentlength=133 gap=12 // Protel DXP Scope 1 Expression Was: All and (Not (OnLayer('Bottom Overlay') or OnLayer('Top Overlay') or InComponentClass('Fid')))
BoardOutlineClearance BoardOutlineClearance_1 [All] p0: scope1count=1 scope1_0_kind=Net scope1_0_value=GND scope2count=1 scope2_0_kind=Board scope2_0_value=Board commentlength=0 gap=8
BoardOutlineClearance BoardOutlineClearance_1 [InNet('GND')] p1: gap=8 ignorepadtopadclearanceinfootprint=FALSE
BoardOutlineClearance [All and (Not (OnLayer('Bottom Overlay') or OnLayer('Top Overlay') or InComponentClass('Fid')))] p2: gap=12 ignorepadtopadclearanceinfootprint=FALSE except(0: Text-OutlineEdge; 10: Via-OutlineEdge)
Clearance 100E_1 [All] p0 off: scope1count=1 scope1_0_kind=Board scope1_0_value=Board scope2count=1 scope2_0_kind=Board scope2_0_value=Board commentlength=88 gap=8 // Protel DXP Scope 2 Expression Was: (OnLayer('Bottom Layer') or OnLayer('Top Layer'))
Clearance INNERlayer [All] p0 off: scope1count=1 scope1_0_kind=Board scope1_0_value=Board scope2count=1 scope2_0_kind=Board scope2_0_value=Board commentlength=75 gap=8 // Protel DXP Scope 1 Expression Was: (OnLayer('pwr1') or OnLayer('pwr2'))
Clearance "SAME NET" [All] p0: scope1count=1 scope1_0_kind=Board scope1_0_value=Board scope2count=1 scope2_0_kind=Board scope2_0_value=Board commentlength=0 gap=0
Clearance [All] p0: scope1count=1 scope1_0_kind=Board scope1_0_value=Board scope2count=1 scope2_0_kind=Board scope2_0_value=Board commentlength=0 gap=1
Clearance 50E_INNERlayer [All] p0 off: scope1count=1 scope1_0_kind=Board scope1_0_value=Board scope2count=1 scope2_0_kind=Board scope2_0_value=Board commentlength=75 gap=4.2 // Protel DXP Scope 1 Expression Was: (OnLayer('sig1') or OnLayer('Sig2'))
Clearance 100E [All] p0 off: scope1count=1 scope1_0_kind=Board scope1_0_value=Board scope2count=1 scope2_0_kind=Board scope2_0_value=Board commentlength=75 gap=8 // Protel DXP Scope 2 Expression Was: (OnLayer('Sig1') or OnLayer('Sig2'))
Clearance AOP_Sig [All] p0 off: scope1count=1 scope1_0_kind=Board scope1_0_value=Board scope2count=1 scope2_0_kind=Board scope2_0_value=Board commentlength=75 gap=4 // Protel DXP Scope 2 Expression Was: (OnLayer('sig1') or OnLayer('sig2'))
Clearance AOP_T-B [All] p0 off: scope1count=1 scope1_0_kind=Board scope1_0_value=Board scope2count=1 scope2_0_kind=Board scope2_0_value=Board commentlength=88 gap=4 // Protel DXP Scope 2 Expression Was: (OnLayer('Bottom Layer') or OnLayer('Top Layer'))
Clearance 90E_OUTSIDE [All] p0 off: scope1count=1 scope1_0_kind=Board scope1_0_value=Board scope2count=1 scope2_0_kind=Board scope2_0_value=Board commentlength=48 gap=6 // Protel DXP Scope 2 Expression Was: OnOutside
Clearance RF_TRACE [All] p0: scope1count=1 scope1_0_kind=NetClass scope1_0_value=RF scope2count=1 scope2_0_kind=Board scope2_0_value=Board commentlength=0 gap=4
Clearance Keepout [All] p0 off: scope1count=1 scope1_0_kind=Board scope1_0_value=Board scope2count=1 scope2_0_kind=Board scope2_0_value=Board commentlength=66 gap=0.01 // Protel DXP Scope 1 Expression Was: (OnLayer('Keep-Out Layer'))
Clearance Keepout [(OnLayer('Keep-Out Layer'))] p1: gap=0.01 ignorepadtopadclearanceinfootprint=FALSE except(5.9: THPad-THPad; 7: Arc-THPad Track-THPad THPad-Via; 8: THPad-Fill THPad-Poly THPad-Region)
Clearance RF_TRACE [InNetClass('RF')] p2: gap=4 ignorepadtopadclearanceinfootprint=FALSE except(0: Arc-Hole Track-Hole SMDPad-Hole THPad-Hole Via-Hole Fill-Hole Poly-Hole Region-Hole Text-Hole; 2: Arc-Text Track-Text SMDPad-Text THPad-Text Via-Text Fill-Text Poly-Text Region-Text Text-Text; 5.9: THPad-THPad; 6: SMDPad-Fill SMDPad-Poly SMDPad-Region Via-Fill Via-Poly Via-Region; 7: Arc-THPad Track-THPad THPad-Via; 8: THPad-Fill THPad-Poly THPad-Region; 8.92: Arc-Fill Arc-Poly Arc-Region Track-Fill Track-Poly Track-Region; 15: Fill-Fill Fill-Poly Fill-Region Poly-Poly Poly-Region Region-Region)
Clearance AOP_T-B [WithinRoom('BGA') vs (OnLayer('Bottom Layer') or OnLayer('Top Layer'))] p3: gap=4 ignorepadtopadclearanceinfootprint=TRUE except(0: Arc-Hole Track-Hole SMDPad-Hole THPad-Hole Via-Hole Fill-Hole Poly-Hole Region-Hole Text-Hole; 3.8: SMDPad-Via; 3.9: Arc-Via Track-Via; 5.9: THPad-THPad; 7: Arc-THPad Track-THPad THPad-Via; 8: THPad-Fill THPad-Poly THPad-Region Fill-Fill Fill-Poly Fill-Region Poly-Poly Poly-Region Region-Region)
Clearance AOP_Sig [WithinRoom('BGA') vs (OnLayer('sig1') or OnLayer('sig2'))] p4: gap=4 ignorepadtopadclearanceinfootprint=FALSE except(0: Arc-Hole Track-Hole SMDPad-Hole THPad-Hole Via-Hole Fill-Hole Poly-Hole Region-Hole Text-Hole; 3.5: Arc-Arc Arc-Track Arc-Via Arc-Text Track-Track Track-Via Track-Text SMDPad-Text THPad-Text Via-Via Via-Text Fill-Text Poly-Text Region-Text Text-Text; 3.8: SMDPad-Via; 5.9: THPad-THPad; 7: Arc-THPad Track-THPad THPad-Via; 8: SMDPad-THPad THPad-Fill THPad-Poly THPad-Region; 15: Fill-Fill Fill-Poly Fill-Region Poly-Poly Poly-Region Region-Region)
Clearance 50E_INNERlayer [(OnLayer('sig1') or OnLayer('Sig2'))] p5: gap=4.2 ignorepadtopadclearanceinfootprint=TRUE except(0: Arc-Hole Track-Hole SMDPad-Hole THPad-Hole Via-Hole Fill-Hole Poly-Hole Region-Hole Text-Hole; 2: SMDPad-Text Fill-Text Poly-Text Region-Text Text-Text; 3.5: Arc-Via Track-Via; 5.9: THPad-THPad; 6: SMDPad-Fill SMDPad-Poly SMDPad-Region; 7: Arc-THPad Track-THPad THPad-Via; 8: Arc-Fill Arc-Poly Arc-Region Track-Fill Track-Poly Track-Region THPad-Fill THPad-Poly THPad-Region; 12: Fill-Fill Fill-Poly Fill-Region Poly-Poly Poly-Region Region-Region)
Clearance INNERlayer [(OnLayer('pwr1') or OnLayer('pwr2'))] p6: gap=8 ignorepadtopadclearanceinfootprint=TRUE except(0: Arc-Hole Track-Hole SMDPad-Hole THPad-Hole Via-Hole Fill-Hole Poly-Hole Region-Hole Text-Hole; 2: SMDPad-Text Fill-Text Poly-Text Region-Text Text-Text; 4: Via-Fill Via-Poly Via-Region; 4.2: Arc-Text Track-Text THPad-Text Via-Via Via-Text; 5: THPad-Fill THPad-Poly THPad-Region; 5.9: THPad-THPad; 6: Arc-Via Arc-Fill Arc-Poly Arc-Region Track-Via Track-Fill Track-Poly Track-Region; 7: THPad-Via; 12: Fill-Fill Fill-Poly Fill-Region Poly-Poly Poly-Region Region-Region)
Clearance 100E [InDifferentialPairClass('100E') vs (OnLayer('Sig1') or OnLayer('Sig2'))] p7: gap=8 ignorepadtopadclearanceinfootprint=FALSE except(0: Arc-Hole Track-Hole SMDPad-Hole THPad-Hole Via-Hole Fill-Hole Poly-Hole Region-Hole Text-Hole; 2: Arc-Text Track-Text THPad-Text Via-Text Fill-Text Poly-Text Region-Text Text-Text; 4: Arc-SMDPad Track-SMDPad SMDPad-SMDPad SMDPad-THPad SMDPad-Via SMDPad-Text Via-Fill Via-Poly Via-Region; 5: Arc-Via Track-Via; 5.9: THPad-THPad; 6: SMDPad-Fill SMDPad-Poly SMDPad-Region Fill-Fill Fill-Poly Fill-Region Poly-Poly Poly-Region Region-Region; 7: Arc-THPad Track-THPad THPad-Via; 16: Arc-Arc Arc-Track Track-Track)
Clearance 100E_1 [InDifferentialPairClass('100E') vs (OnLayer('Bottom Layer') or OnLayer('Top Layer'))] p8: gap=8 ignorepadtopadclearanceinfootprint=FALSE except(0: Arc-Hole Track-Hole SMDPad-Hole THPad-Hole Via-Hole Fill-Hole Poly-Hole Region-Hole Text-Hole; 2: Arc-Text Track-Text THPad-Text Via-Text Fill-Text Poly-Text Region-Text Text-Text; 4: Arc-SMDPad Track-SMDPad SMDPad-SMDPad SMDPad-THPad SMDPad-Via SMDPad-Text Via-Fill Via-Poly Via-Region; 5: Arc-Via Track-Via; 5.9: THPad-THPad; 6: SMDPad-Fill SMDPad-Poly SMDPad-Region Fill-Fill Fill-Poly Fill-Region Poly-Poly Poly-Region Region-Region; 7: Arc-THPad Track-THPad THPad-Via; 11: Arc-Arc Arc-Track Track-Track)
Clearance 90E_OUTSIDE [InDifferentialPairClass('90E') vs OnOutside] p9: gap=6 ignorepadtopadclearanceinfootprint=TRUE except(0: Arc-Hole Track-Hole SMDPad-Hole THPad-Hole Via-Hole Fill-Fill Fill-Poly Fill-Region Fill-Hole Poly-Poly Poly-Region Poly-Hole Region-Region Region-Hole Text-Hole; 2: Arc-Text Track-Text SMDPad-Text THPad-Text Via-Text Fill-Text Poly-Text Region-Text Text-Text; 3.8: SMDPad-Via; 4: Arc-SMDPad Track-SMDPad SMDPad-SMDPad Via-Via Via-Fill Via-Poly Via-Region; 4.5: Arc-Arc Arc-Track Arc-Via Track-Track Track-Via; 5.9: THPad-THPad; 7: Arc-THPad Track-THPad SMDPad-THPad THPad-Via; 8: THPad-Fill THPad-Poly THPad-Region)
Clearance [All] p10: gap=1 ignorepadtopadclearanceinfootprint=TRUE except(0: Arc-Hole Track-Hole SMDPad-Hole THPad-Hole Via-Hole Fill-Hole Poly-Hole Region-Hole Text-Hole; 3.8: SMDPad-Via; 3.9: Arc-Via Track-Via; 4: Arc-SMDPad Track-SMDPad SMDPad-SMDPad Via-Via Via-Fill Via-Poly Via-Region; 4.5: Arc-Arc Arc-Track Track-Track; 5: Arc-Fill Arc-Poly Arc-Region Track-Fill Track-Poly Track-Region; 5.9: THPad-THPad; 6: SMDPad-Fill SMDPad-Poly SMDPad-Region; 7: Arc-THPad Track-THPad SMDPad-THPad THPad-Via; 8: THPad-Fill THPad-Poly THPad-Region; 12: Fill-Fill Fill-Poly Fill-Region Poly-Poly Poly-Region Region-Region)
Clearance "SAME NET" [All] p11: gap=0 ignorepadtopadclearanceinfootprint=FALSE except(0.5: SMDPad-Text; 5.9: THPad-THPad)
ComponentClearance ComponentClearance_THtoTH [All] p0 off: scope1count=1 scope1_0_kind=Board scope1_0_value=Board scope2count=1 scope2_0_kind=Board scope2_0_value=Board commentlength=54 gap=20 collisioncheckmode=3 // Protel DXP Scope 2 Expression Was: IsThruComponent
ComponentClearance ComponentClearance_THtoSMT [All] p0 off: scope1count=1 scope1_0_kind=Board scope1_0_value=Board scope2count=1 scope2_0_kind=Board scope2_0_value=Board commentlength=53 gap=5 collisioncheckmode=3 // Protel DXP Scope 2 Expression Was: IsSMTComponent
ComponentClearance ComponentClearance_SmallPassives [All] p0 off: scope1count=1 scope1_0_kind=Board scope1_0_value=Board scope2count=1 scope2_0_kind=Board scope2_0_value=Board commentlength=508 gap=10 collisioncheckmode=3 // Protel DXP Scope 2 Expression Was: HasFootprint('0201*') or HasFootprint('0402*') or HasFootprint('0508') or HasFootprint('0603*') or HasFootprint('0612') or HasFootprint('0805*') or HasFootprint('0815*') or HasFootprint('0830*') or HasFootprint('1206*') or HasFootprint('1210*') or HasFootprint('1808*') or HasFootprint('1812*') or HasFootprint('1825*') or HasFootprint('2010*') or HasFootprint('2220*') or HasFootprint('2225*') or HasFootprint('2512*') or HasFootprint('2728*') or HasFootprint('3518*')
ComponentClearance ComponentClearance_MountingHoles [All] p0: scope1count=1 scope1_0_kind=ComponentClass scope1_0_value="Mounting Holes" scope2count=1 scope2_0_kind=Board scope2_0_value=Board commentlength=0 gap=20 collisioncheckmode=3
ComponentClearance ComponentClearance_ScrewToNut [All] p0 off: scope1count=1 scope1_0_kind=Board scope1_0_value=Board scope2count=1 scope2_0_kind=Board scope2_0_value=Board commentlength=71 gap=5 collisioncheckmode=3 // Protel DXP Scope 2 Expression Was: (HasFootprint('Keystone_1902C'))
ComponentClearance ComponentClearance_Logo [All] p0: scope1count=1 scope1_0_kind=ComponentClass scope1_0_value=Logo scope2count=1 scope2_0_kind=Board scope2_0_value=Board commentlength=0 gap=50 collisioncheckmode=3
ComponentClearance ComponentClearance_Shunt [All] p0: scope1count=1 scope1_0_kind=ComponentClass scope1_0_value=Header scope2count=1 scope2_0_kind=ComponentClass scope2_0_value=Shunt commentlength=0 gap=1 collisioncheckmode=3
ComponentClearance ComponentClearance_MountingHoles_FiducialMarks [All] p0: scope1count=1 scope1_0_kind=ComponentClass scope1_0_value="Mounting Holes" scope2count=1 scope2_0_kind=ComponentClass scope2_0_value=FiducialMark commentlength=0 gap=50 collisioncheckmode=3
ComponentClearance [All] p0: scope1count=1 scope1_0_kind=Board scope1_0_value=Board scope2count=1 scope2_0_kind=Board scope2_0_value=Board commentlength=0 gap=1 collisioncheckmode=3
ComponentClearance ComponentClearance_R188_204 [All] p0: scope1count=1 scope1_0_kind=Component scope1_0_value=R188 scope2count=1 scope2_0_kind=Component scope2_0_value=R204 commentlength=0 gap=-1 collisioncheckmode=3
ComponentClearance ComponentClearance_R199_187 [All] p0 off: scope1count=1 scope1_0_kind=Board scope1_0_value=Board scope2count=1 scope2_0_kind=Board scope2_0_value=Board commentlength=80 gap=-1 collisioncheckmode=3 // Protel DXP Scope 1 Expression Was: InComponent('J11') or InComponent('TP20')
ComponentClearance ComponentClearance_R199_187 [InComponent('J11') or InComponent('TP20')] p1: gap=-1 collisioncheckmode=3 verticalgap=10 showdistances=FALSE
ComponentClearance ComponentClearance_R188_204 [InComponent('R188') vs InComponent('R204')] p2: gap=-1 collisioncheckmode=3 verticalgap=10 showdistances=FALSE
ComponentClearance [All] p3: gap=1 collisioncheckmode=3 verticalgap=10 showdistances=FALSE
ComponentClearance ComponentClearance_MountingHoles_FiducialMarks [InComponentClass('Mounting Holes') vs InComponentClass('FiducialMark')] p4: gap=50 collisioncheckmode=3 verticalgap=10 showdistances=FALSE
ComponentClearance ComponentClearance_Shunt [InComponentClass('Header') vs InComponentClass('Shunt')] p5: gap=1 collisioncheckmode=3 verticalgap=0 showdistances=FALSE
ComponentClearance ComponentClearance_Logo [InComponentClass('Logo')] p6: gap=50 collisioncheckmode=3 verticalgap=10 showdistances=FALSE
ComponentClearance ComponentClearance_ScrewToNut [(HasFootprint('NY PMS 440 0025 PH')) vs (HasFootprint('Keystone_1902C'))] p7: gap=5 collisioncheckmode=3 verticalgap=10 showdistances=FALSE
ComponentClearance ComponentClearance_MountingHoles [InComponentClass('Mounting Holes')] p8: gap=20 collisioncheckmode=3 verticalgap=100000 showdistances=FALSE
ComponentClearance ComponentClearance_SmallPassives [HasFootprint('0201*') or HasFootprint('0402*') or HasFootprint('0508') or HasFootprint('0603*') or HasFootprint('0612') or HasFootprint('0805*') or HasFootprint('0815*') or HasFootprint('0830*') or HasFootprint('1206*') or HasFootprint('1210*') or HasFootprint('1808*') or HasFootprint('1812*') or HasFootprint('1825*') or HasFootprint('2010*') or HasFootprint('2220*') or HasFootprint('2225*') or HasFootprint('2512*') or HasFootprint('2728*') or HasFootprint('3518*') vs HasFootprint('0201*') or HasFootprint('0402*') or HasFootprint('0508') or HasFootprint('0603*') or HasFootprint('0612') or HasFootprint('0805*') or HasFootprint('0815*') or HasFootprint('0830*') or HasFootprint('1206*') or HasFootprint('1210*') or HasFootprint('1808*') or HasFootprint('1812*') or HasFootprint('1825*') or HasFootprint('2010*') or HasFootprint('2220*') or HasFootprint('2225*') or HasFootprint('2512*') or HasFootprint('2728*') or HasFootprint('3518*')] p9: gap=10 collisioncheckmode=3 verticalgap=10 showdistances=FALSE
ComponentClearance ComponentClearance_THtoSMT [IsThruComponent vs IsSMTComponent] p10: gap=5 collisioncheckmode=3 verticalgap=20 showdistances=FALSE
ComponentClearance ComponentClearance_THtoTH [IsThruComponent vs IsThruComponent] p11: gap=20 collisioncheckmode=3 verticalgap=30 showdistances=FALSE
DiffPairsRouting Diff_120E [All] p0 off: scope1count=1 scope1_0_kind=Board scope1_0_value=Board scope2count=1 scope2_0_kind=Board scope2_0_value=Board commentlength=70 // Protel DXP Scope 1 Expression Was: InDifferentialPairClass('120E')
DiffPairsRouting Diff_100E [All] p0 off: scope1count=1 scope1_0_kind=Board scope1_0_value=Board scope2count=1 scope2_0_kind=Board scope2_0_value=Board commentlength=70 // Protel DXP Scope 1 Expression Was: InDifferentialPairClass('100E')
DiffPairsRouting Diff_90E [All] p0 off: scope1count=1 scope1_0_kind=Board scope1_0_value=Board scope2count=1 scope2_0_kind=Board scope2_0_value=Board commentlength=69 // Protel DXP Scope 1 Expression Was: InDifferentialPairClass('90E')
DiffPairsRouting Diff_100E [InDifferentialPairClass('100E')] p1: maxlimit=10 minlimit=7 mostfreqgap=10 toplayer_maxgap=7 toplayer_prefgap=7 toplayer_minwidth=4 toplayer_maxwidth=4 toplayer_prefwidth=4 midlayer1_mingap=10 midlayer1_minwidth=15 midlayer1_maxwidth=15 midlayer1_prefwidth=15 midlayer2_mingap=8 midlayer2_maxgap=8 midlayer2_prefgap=8 midlayer2_minwidth=3.5 midlayer2_maxwidth=3.5 midlayer2_prefwidth=3.5 midlayer3_mingap=10 midlayer3_minwidth=15 midlayer3_maxwidth=15 midlayer3_prefwidth=15 midlayer6_mingap=10 midlayer6_minwidth=15 midlayer6_maxwidth=15 midlayer6_prefwidth=15 midlayer7_mingap=8 midlayer7_maxgap=8 midlayer7_prefgap=8 midlayer7_minwidth=3.5 midlayer7_maxwidth=3.5 midlayer7_prefwidth=3.5 midlayer8_mingap=10 midlayer8_minwidth=15 midlayer8_maxwidth=15 midlayer8_prefwidth=15 bottomlayer_maxgap=7 bottomlayer_prefgap=7 bottomlayer_minwidth=4 bottomlayer_maxwidth=4 bottomlayer_prefwidth=4 maxuncoupledlength=500
DiffPairsRouting Diff_90E [InDifferentialPairClass('90E')] p2: maxlimit=100 minlimit=4.5 mostfreqgap=10 toplayer_maxgap=4.5 toplayer_prefgap=4.5 toplayer_minwidth=4 toplayer_maxwidth=4 toplayer_prefwidth=4 midlayer1_mingap=10 midlayer1_minwidth=15 midlayer1_maxwidth=15 midlayer1_prefwidth=15 midlayer2_mingap=6 midlayer2_maxgap=6 midlayer2_prefgap=6 midlayer2_minwidth=4 midlayer2_maxwidth=4 midlayer2_prefwidth=4 midlayer3_mingap=10 midlayer3_minwidth=15 midlayer3_maxwidth=15 midlayer3_prefwidth=15 midlayer6_mingap=10 midlayer6_minwidth=15 midlayer6_maxwidth=15 midlayer6_prefwidth=15 midlayer7_mingap=6 midlayer7_maxgap=6 midlayer7_prefgap=6 midlayer7_minwidth=4 midlayer7_maxwidth=4 midlayer7_prefwidth=4 midlayer8_mingap=10 midlayer8_minwidth=15 midlayer8_maxwidth=15 midlayer8_prefwidth=15 bottomlayer_maxgap=4.5 bottomlayer_prefgap=4.5 bottomlayer_minwidth=4 bottomlayer_maxwidth=4 bottomlayer_prefwidth=4 maxuncoupledlength=1000
DiffPairsRouting Diff_120E [InDifferentialPairClass('120E')] p3: maxlimit=10 minlimit=6.1 mostfreqgap=10 toplayer_maxgap=6.1 toplayer_prefgap=6.1 toplayer_minwidth=4 toplayer_maxwidth=4 toplayer_prefwidth=4 midlayer1_mingap=10 midlayer1_minwidth=15 midlayer1_maxwidth=15 midlayer1_prefwidth=15 midlayer2_mingap=10 midlayer2_minwidth=15 midlayer2_maxwidth=15 midlayer2_prefwidth=15 midlayer3_mingap=10 midlayer3_minwidth=15 midlayer3_maxwidth=15 midlayer3_prefwidth=15 midlayer6_mingap=10 midlayer6_minwidth=15 midlayer6_maxwidth=15 midlayer6_prefwidth=15 midlayer7_mingap=10 midlayer7_minwidth=15 midlayer7_maxwidth=15 midlayer7_prefwidth=15 midlayer8_mingap=10 midlayer8_minwidth=15 midlayer8_maxwidth=15 midlayer8_prefwidth=15 bottomlayer_maxgap=6.1 bottomlayer_prefgap=6.1 bottomlayer_minwidth=4 bottomlayer_maxwidth=4 bottomlayer_prefwidth=4 maxuncoupledlength=500
FabricationTestPointUsage TestPointUsage [All] p0: scope1count=1 scope1_0_kind=Board scope1_0_value=Board scope2count=1 scope2_0_kind=Board scope2_0_value=Board commentlength=0 valid=2 allowmultiple=FALSE
FabricationTestPointUsage TestPointUsage [All] p1: valid=2 allowmultiple=FALSE
FabricationTestpoint Testpoint [All] p0: scope1count=1 scope1_0_kind=Board scope1_0_value=Board scope2count=1 scope2_0_kind=Board scope2_0_value=Board commentlength=0 side=3 testpointundercomponent=TRUE minsize=40 maxsize=100 preferedsize=60 minholesize=0 maxholesize=40 preferedholesize=32 testpointgrid=1
FabricationTestpoint Testpoint [All] p1: side=3 testpointundercomponent=TRUE minsize=40 maxsize=100 preferedsize=60 minholesize=0 maxholesize=40 preferedholesize=32 testpointgrid=1 allowsidetop=TRUE allowsidebottom=TRUE usegrid=TRUE gridtolerance=0.01
FanoutControl Fanout_Small [All] p0 off: scope1count=1 scope1_0_kind=Board scope1_0_value=Board scope2count=1 scope2_0_kind=Board scope2_0_value=Board commentlength=84 // Protel DXP Scope 1 Expression Was: (CompPinCount < 5)   Fanout_Small (Default Rule)
FanoutControl Fanout_Default [All] p0: scope1count=1 scope1_0_kind=Board scope1_0_value=Board scope2count=1 scope2_0_kind=Board scope2_0_value=Board commentlength=30 // Fanout_Default (Default Rule)
FanoutControl Fanout_SOIC [All] p0 off: scope1count=1 scope1_0_kind=Board scope1_0_value=Board scope2count=1 scope2_0_kind=Board scope2_0_value=Board commentlength=71 // Protel DXP Scope 1 Expression Was: IsSOIC   Fanout_SOIC (Default Rule)
FanoutControl Fanout_BGA [All] p0 off: scope1count=1 scope1_0_kind=Board scope1_0_value=Board scope2count=1 scope2_0_kind=Board scope2_0_value=Board commentlength=69 // Protel DXP Scope 1 Expression Was: IsBGA   Fanout_BGA (Default Rule)
FanoutControl Fanout_LCC [All] p0 off: scope1count=1 scope1_0_kind=Board scope1_0_value=Board scope2count=1 scope2_0_kind=Board scope2_0_value=Board commentlength=69 // Protel DXP Scope 1 Expression Was: IsLCC   Fanout_LCC (Default Rule)
FanoutControl Fanout_LCC [IsLCC] p1: bgadir=Out bgaviamode=Centered fanoutstyle=Auto fanoutdirection=Alternating viagrid=1 // Fanout_LCC (Default Rule)
FanoutControl Fanout_BGA [IsBGA] p2: bgadir=Out bgaviamode=Centered fanoutstyle=Auto fanoutdirection=Alternating viagrid=1 // Fanout_BGA (Default Rule)
FanoutControl Fanout_Default [All] p4: bgadir=Out bgaviamode=Centered fanoutstyle=Auto fanoutdirection=Alternating viagrid=1 // Fanout_Default (Default Rule)
FanoutControl Fanout_Small [(CompPinCount < 5)] p5: bgadir=Out bgaviamode=Centered fanoutstyle=Auto fanoutdirection=OutThenIn viagrid=1 // Fanout_Small (Default Rule)
Height [All] p0: scope1count=1 scope1_0_kind=Board scope1_0_value=Board scope2count=1 scope2_0_kind=Board scope2_0_value=Board commentlength=0
HoleSize [All] p0: scope1count=1 scope1_0_kind=Board scope1_0_value=Board scope2count=1 scope2_0_kind=Board scope2_0_value=Board commentlength=0 absolutevalues=TRUE maxlimit=251 minlimit=5.9 maxpercent=80.000 minpercent=20.000
HoleSize [All] p1: absolutevalues=TRUE maxlimit=251 minlimit=5.9 maxpercent=80.000 minpercent=20.000
HoleToHoleClearance [All] p0: scope1count=1 scope1_0_kind=Board scope1_0_value=Board scope2count=1 scope2_0_kind=Board scope2_0_value=Board commentlength=0
LayerPairs [All] p0: scope1count=1 scope1_0_kind=Board scope1_0_value=Board scope2count=1 scope2_0_kind=Board scope2_0_value=Board commentlength=0 enforce=TRUE
MatchedLengths [All] p0: scope1count=1 scope1_0_kind=NetClass scope1_0_value=LVDS_IC scope2count=1 scope2_0_kind=Board scope2_0_value=Board commentlength=0 tolerance=20 amplitude=200 gap=20 style=90-Degree
MatchedLengths USB [All] p0 off: scope1count=1 scope1_0_kind=Board scope1_0_value=Board scope2count=1 scope2_0_kind=Board scope2_0_value=Board commentlength=60 tolerance=5 amplitude=200 gap=20 style=90-Degree // Protel DXP Scope 1 Expression Was: InxSignalClass('USB')
MatchedLengths JTAG [All] p0 off: scope1count=1 scope1_0_kind=Board scope1_0_value=Board scope2count=1 scope2_0_kind=Board scope2_0_value=Board commentlength=61 tolerance=100 amplitude=200 gap=20 style=90-Degree // Protel DXP Scope 1 Expression Was: InxSignalClass('JTAG')
MatchedLengths SPI [All] p0 off: scope1count=1 scope1_0_kind=Board scope1_0_value=Board scope2count=1 scope2_0_kind=Board scope2_0_value=Board commentlength=70 tolerance=200 amplitude=200 gap=20 style=90-Degree // Protel DXP Scope 1 Expression Was: InxSignalClass('SPI & HOSTINT')
MatchedLengths QSPI [All] p0 off: scope1count=1 scope1_0_kind=Board scope1_0_value=Board scope2count=1 scope2_0_kind=Board scope2_0_value=Board commentlength=61 tolerance=100 amplitude=200 gap=20 style=90-Degree // Protel DXP Scope 1 Expression Was: InxSignalClass('QSPI')
MatchedLengths [InNetClass('LVDS_IC')] p1: tolerance=20 checknetsindiffpair=FALSE checkdiffpairvsdiffpair=TRUE checkxsignals=TRUE checkothers=TRUE
MatchedLengths USB [InxSignalClass('USB')] p2: tolerance=5 checknetsindiffpair=TRUE checkdiffpairvsdiffpair=FALSE checkxsignals=FALSE checkothers=FALSE
MatchedLengths QSPI [InxSignalClass('QSPI')] p3: tolerance=100 checknetsindiffpair=FALSE checkdiffpairvsdiffpair=TRUE checkxsignals=TRUE checkothers=TRUE
MatchedLengths SPI [InxSignalClass('SPI & HOSTINT')] p4: tolerance=200 checknetsindiffpair=FALSE checkdiffpairvsdiffpair=TRUE checkxsignals=TRUE checkothers=TRUE
MatchedLengths JTAG [InxSignalClass('JTAG')] p5: tolerance=100 checknetsindiffpair=FALSE checkdiffpairvsdiffpair=TRUE checkxsignals=TRUE checkothers=TRUE
MinimumAnnularRing [All] p0: scope1count=1 scope1_0_kind=Board scope1_0_value=Board scope2count=1 scope2_0_kind=Board scope2_0_value=Board commentlength=0 minimumring=3
MinimumAnnularRing MinimumAnnularRing_ThermalPadVias [All] p0 off: scope1count=1 scope1_0_kind=Board scope1_0_value=Board scope2count=1 scope2_0_kind=Board scope2_0_value=Board commentlength=63 minimumring=3 // Protel DXP Scope 1 Expression Was: IsVia and InAnyComponent
MinimumAnnularRing MinimumAnnularRing_ThermalPadVias [IsVia and InAnyComponent] p1: minimumring=3
MinimumAnnularRing [All] p2: minimumring=3
MinimumSolderMaskSliver [All] p0: scope1count=1 scope1_0_kind=Board scope1_0_value=Board scope2count=1 scope2_0_kind=Board scope2_0_value=Board commentlength=0
MinimumSolderMaskSliver [All] p1: minsoldermaskwidth=2.5
NetAntennae [All] p0: scope1count=1 scope1_0_kind=Board scope1_0_value=Board scope2count=1 scope2_0_kind=Board scope2_0_value=Board commentlength=0
PasteMaskExpansion [All] p0: scope1count=1 scope1_0_kind=Board scope1_0_value=Board scope2count=1 scope2_0_kind=Board scope2_0_value=Board commentlength=0 expansion=0
PlaneClearance [All] p0: scope1count=1 scope1_0_kind=Board scope1_0_value=Board scope2count=1 scope2_0_kind=Board scope2_0_value=Board commentlength=0 clearance=20
PlaneConnect [All] p0: scope1count=1 scope1_0_kind=Board scope1_0_value=Board scope2count=1 scope2_0_kind=Board scope2_0_value=Board commentlength=0 planeconnectstyle=Direct reliefexpansion=10 reliefentries=4 reliefconductorwidth=10 reliefairgap=10
PlaneConnect [All] p1: planeconnectstyle=Direct reliefexpansion=10 reliefentries=4 reliefconductorwidth=10 reliefairgap=10
PolygonConnect [All] p0: scope1count=1 scope1_0_kind=Board scope1_0_value=Board scope2count=1 scope2_0_kind=Board scope2_0_value=Board commentlength=0 connectstyle=Direct reliefconductorwidth=10 reliefentries=4 polygonreliefangle="90 Angle"
PolygonConnect [All] p1: connectstyle=Direct reliefconductorwidth=10 reliefentries=4 polygonreliefangle="90 Angle" airgapwidth=10
RoomDefinition PROC091G_Hardware [All] p0: scope1count=1 scope1_0_kind=ComponentClass scope1_0_value=PROC091G_Hardware scope2count=1 scope2_0_kind=Board scope2_0_value=Board commentlength=0 region_x1=44490000 region_y1=53680000 region_x2=50747070 region_y2=59816060 confinementstyle=ConfineIn
RoomDefinition PROC091G_Hardware [InComponentClass('PROC091G_Hardware')] p1: confinementstyle=ConfineIn formatcopy=TRUE lockcomponents=FALSE outline 3757.84,4447.61 4382.71,4447.61 4382.71,3834 3757,3834
RoutingCorners [All] p0: scope1count=1 scope1_0_kind=Board scope1_0_value=Board scope2count=1 scope2_0_kind=Board scope2_0_value=Board commentlength=0 cornerstyle=45-Degree minsetback=100 maxsetback=100
RoutingLayers [All] p0: scope1count=1 scope1_0_kind=Board scope1_0_value=Board scope2count=1 scope2_0_kind=Board scope2_0_value=Board commentlength=0 top layer=Automatic mid layer 1=Automatic mid layer 2=Automatic mid layer 3=Automatic mid layer 6=Automatic mid layer 7=Automatic mid layer 8=Automatic bottom layer=Automatic
RoutingPriority [All] p0: scope1count=1 scope1_0_kind=Board scope1_0_value=Board scope2count=1 scope2_0_kind=Board scope2_0_value=Board commentlength=0
RoutingTopology [All] p0: scope1count=1 scope1_0_kind=Board scope1_0_value=Board scope2count=1 scope2_0_kind=Board scope2_0_value=Board commentlength=0 topology=Shortest
RoutingVias [All] p0: scope1count=1 scope1_0_kind=Board scope1_0_value=Board scope2count=1 scope2_0_kind=Board scope2_0_value=Board commentlength=0 holewidth=8 width=18 viastyle="Through Hole" minholewidth=7.87 minwidth=17 maxholewidth=40 maxwidth=30
RoutingVias ThermalPadVias [All] p0 off: scope1count=1 scope1_0_kind=Board scope1_0_value=Board scope2count=1 scope2_0_kind=Board scope2_0_value=Board commentlength=63 holewidth=7.87 width=19.68 viastyle="Through Hole" minholewidth=7.87 minwidth=19.68 maxholewidth=12.99 maxwidth=23.62 // Protel DXP Scope 1 Expression Was: IsVia and InAnyComponent
RoutingVias [All] p1: holewidth=8 width=18 viastyle="Through Hole" minholewidth=7.87 minwidth=17 maxholewidth=40 maxwidth=30
RoutingVias ThermalPadVias [IsVia and InAnyComponent] p2: holewidth=7.87 width=19.68 viastyle="Through Hole" minholewidth=7.87 minwidth=19.68 maxholewidth=12.99 maxwidth=23.62
ShortCircuit [All] p0: scope1count=1 scope1_0_kind=Board scope1_0_value=Board scope2count=1 scope2_0_kind=Board scope2_0_value=Board commentlength=0 allowed=FALSE
SilkToBoardRegionClearance [All] p0 off: scope1count=1 scope1_0_kind=Board scope1_0_value=Board scope2count=1 scope2_0_kind=Board scope2_0_value=Board commentlength=130 // Protel DXP Scope 1 Expression Was: Not ((IsComment or IsDesignator) And (Hide <> 'False')) and not InRegion(1000,500,4000,800)
SilkToBoardRegionClearance [Not ((IsComment or IsDesignator) And (Hide <> 'False')) and not InRegion(1000,500,4000,800)] p1:
SilkToSilkClearance [All] p0: scope1count=1 scope1_0_kind=Board scope1_0_value=Board scope2count=1 scope2_0_kind=Board scope2_0_value=Board commentlength=0
SilkToSilkClearance [All] p1: silktosilkclearance=0
SilkToSolderMaskClearance "Silk to Solder Mask Opening" [All] p0: scope1count=1 scope1_0_kind=Board scope1_0_value=Board scope2count=1 scope2_0_kind=Board scope2_0_value=Board commentlength=0
SilkToSolderMaskClearance SilkToComponentPadClearance [All] p0 off: scope1count=1 scope1_0_kind=Board scope1_0_value=Board scope2count=1 scope2_0_kind=Board scope2_0_value=Board commentlength=87 // Protel DXP Scope 1 Expression Was: (IsPad or IsFill or IsRegion) and InAnycomponent
SilkToSolderMaskClearance SilkToComponentPadClearance [(IsPad or IsFill or IsRegion) and InAnycomponent] p1: minsilkscreentomaskgap=3 clearancetoexposedcopper=TRUE
SilkToSolderMaskClearance "Silk to Solder Mask Opening" [All] p2: minsilkscreentomaskgap=3 clearancetoexposedcopper=FALSE
SolderMaskExpansion [All] p0: scope1count=1 scope1_0_kind=Board scope1_0_value=Board scope2count=1 scope2_0_kind=Board scope2_0_value=Board commentlength=0 expansion=1.97
SolderMaskExpansion [All] p1: expansion=1.97
UnRoutedNet [All] p0: scope1count=1 scope1_0_kind=Board scope1_0_value=Board scope2count=1 scope2_0_kind=Board scope2_0_value=Board commentlength=0
UnpouredPolygon [All] p0: scope1count=1 scope1_0_kind=Board scope1_0_value=Board scope2count=1 scope2_0_kind=Board scope2_0_value=Board commentlength=0
Width RF [All] p0: scope1count=1 scope1_0_kind=NetClass scope1_0_value=RF scope2count=1 scope2_0_kind=Board scope2_0_value=Board commentlength=0 maxlimit=100 minlimit=5.5 preferedwidth=10
Width [All] p0: scope1count=1 scope1_0_kind=Board scope1_0_value=Board scope2count=1 scope2_0_kind=Board scope2_0_value=Board commentlength=0 maxlimit=100 minlimit=4 preferedwidth=6
Width RF [InNetClass('RF')] p1: maxlimit=100 minlimit=5.5 preferedwidth=10 toplayer_prefwidth=14.15 midlayer1_minwidth=10 midlayer1_maxwidth=10 midlayer2_minwidth=10 midlayer2_maxwidth=10 midlayer3_minwidth=10 midlayer3_maxwidth=10 midlayer6_minwidth=10 midlayer6_maxwidth=10 midlayer7_minwidth=10 midlayer7_maxwidth=10 midlayer8_minwidth=10 midlayer8_maxwidth=10 bottomlayer_minwidth=10 bottomlayer_maxwidth=10 minimp=50.000000 maximp=50.000000 favimp=50.000000
Width [All] p2: maxlimit=100 minlimit=4 preferedwidth=6 toplayer_maxwidth=40 toplayer_prefwidth=5.5 midlayer1_minwidth=4.2 midlayer1_maxwidth=20 midlayer1_prefwidth=4.2 midlayer2_minwidth=4.2 midlayer2_maxwidth=10 midlayer2_prefwidth=4.2 midlayer7_minwidth=4.2 midlayer7_maxwidth=20 midlayer7_prefwidth=4.2 midlayer8_minwidth=6 midlayer8_prefwidth=10 bottomlayer_maxwidth=40 bottomlayer_prefwidth=5.5 minimp=50.000000 maximp=50.000000 favimp=50.000000
15 further rules are at their usual default settings.

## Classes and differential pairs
component class PROC091G_Hardware: Designator22_1 Designator23 FID2 ZZ1 ZZ2 ZZ3 ZZ4 ZZ5.1 ZZ5.2
component class PROC091G_RST_GPIOs_I2C: C6 C9 C10 C11 C12 C13 C38 C39 C72 C120 C125 J3 LD2 LD3 LD5 Q1 R13 R18 R38 R42 R51 R57 R67 R68 R69 R70 R71 R72 R73 R77 R78 R80 R81 R82 R93 R96 R97 R98 R107 R108 R111 R124 R125 R129 R177 R178 SW2 SW3 TP15 TP20 U5 U6 U7 U16 Y4
component class PROC091G_PMIC: C30 C31 C32 C33 C34 C44 C45 C46 C47 C50 C51 C52 C53 C111 C112 C113 C121 C124 C131 C132 C133 C134 C135 C136 C137 C138 C139 C140 C141 L2 L3 L4 L5 L11 L12 L13 L14 L15 LD1 R25 R26 R28 R31 R32 R33 R34 R35 R36 R37 R39 R50 R52 R53 R54 R55 R56 TP5 TP12 U1
component class PROC091G_HD_CONN_PWR_SW: C127 C128 C129 D2 FL4 FL11 FL22 J2 J11 R10 R11 R12 R14 R20 R24 R27 R29 R58 R88 R92 R130 R132 R133 R135 R137 R138 R140 R142 R143 R144 R145 R146 R147 R148 R149 R150 R151 R152 R153 R154 R155 R157 R186 R187 R188 R189 R190 RA1 RA2 RA3 RA4 RA5 RA6 RA7 RA8 RA9 TP10 TP13 U19
component class PROC091G_FLASH_USB_TO_UART: C1 C2 C3 C4 C100 C101 C126 D1 FL2 J1 LD4 R6 R15 R19 R40 R41 R43 R44 R45 R46 R47 R48 R49 R60 R64 R65 TP18 TP19 TP26 U3 U9 U18
component class PROC091G_CAN_INTERFACE: C40 C43 C105 C106 C107 C108 C109 C110 FL3 FL12 J8 J10 R66 R74 R104 R105 R106 R114 R115 R116 R117 R118 R119 R120 R121 R122 R123 R126 R127 R128 R134 R136 R139 R141 U11 U12 U13 U17
component class PROC091G_BT_DISPLAY: A1 C5 C7 C8 C15 C16 C17 C18 C19 C20 C21 C22 C23 C24 C25 C26 C27 C28 C29 C35 C36 C37 C41 C86 C93 C99 C104 C114 C115 C116 C117 C118 C119 J4 J6 J7 L1 L6 L7 L8 L9 L10 LD6 R17 R30 R76 R79 R86 R87 R89 R90 R91 R94 R95 R99 R100 R101 R102 R110 R112 R113 R131 R160 R161 R166 R168 R180 R181 R182 R183 R184 R185 TP16 TP27 TP46 U4 U8 U10 U14 Y2 Y3
component class PROC091G_AOP_PWR: C55 C56 C57 C58 C59 C60 C61 C62 C63 C64 C65 C66 C67 C68 C69 C70 C73 C74 C75 C76 C78 C79 C80 C81 C82 C83 C84 C85 C87 C88 C89 C90 C91 C92 C94 C95 C96 C97 C98 C102 C103 TP11
component class PROC091G_AOP_IO: C14 C71 C130 J9 R2 R3 R4 R5 R7 R8 R9 R21 R22 R23 R59 R61 R62 R75 R83 R84 R85 R103 R109 R158 R159 R170 R171 R172 R174 R176 S3 TP2 TP3 TP6 TP7 TP8 TP9 TP14 TP17 U2 Y1
component class PROC091G_ANALOG_MUX: C42 C122 C123 FL14 J5 R1 R16 S1 S2 TP4 U15
component class FiducialMark: FID2
component class AssemblyNote: ZZ1 ZZ2 ZZ3 ZZ4 ZZ5.1 ZZ5.2
differential pair NewDifferentialPair1: +NetJ8_1 -NetJ8_3
differential pair USB: +USB_DP -USB_DM
differential pair NewDifferentialPair2: +NetJ10_1 -NetJ10_3
differential pair AR_LVDS_CLK: +AR_LVDS_CLK_P -AR_LVDS_CLK_N
differential pair AR_LVDS_FRCLK: +AR_LVDS_FRCLK_P -AR_LVDS_FRCLK_N
differential pair AR_LVDS_1: +AR_LVDS_1_P -AR_LVDS_1_N
differential pair AR_LVDS_0: +AR_LVDS_0_P -AR_LVDS_0_N
differential pair AR_LVDS_0_R: +NetJ11_56 -NetJ11_58
differential pair AR_LVDS_1_R: +NetJ11_50 -NetJ11_52
differential pair AR_LVDS_CLK_R: +NetJ11_44 -NetJ11_46
differential pair " ": +NetJ11_26 -NetJ11_28

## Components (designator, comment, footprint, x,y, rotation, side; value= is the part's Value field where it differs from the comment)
A1 "ANT016008LCS2442MA2" FP-ANT016008LCS2442MA2_SMT_ANT-0 7028.91,4589.83 r180 top
C1 "CL05A106MP5NUNC" 0402_070 3044.3,3970.8 r180 top
C2 "GRM033R6YA104KE14D" "FP-GRM033R6YA104KE14D_0201 (0603 Metric)-IPC_C" 3785.88,4170.74 r90 bottom
C3 "GRM033R6YA104KE14D" "FP-GRM033R6YA104KE14D_0201 (0603 Metric)-IPC_C" 3772.95,4125.72 r180 bottom
C4 "CL05A106MP5NUNC" 0402_070 2841.59,4328.91 r90 bottom
C5 "CL03A105MO3NRNH" FP-CL03A105MO3NRNH_0201-IPC_C 6882.81,3977 r180 bottom
C6 "GRM033R6YA104KE14D" "FP-GRM033R6YA104KE14D_0201 (0603 Metric)-IPC_C" 5221.01,4103.02 r0 bottom locked
C7 "CL05A106MP5NUNC" 0402_070 6844.78,3720.79 r0 bottom
C8 "CL03A103KA3NNNC" FP-CL03A103KA3NNNC_0201-IPC_C 6903.19,3719.01 r180 bottom
C9 "GRM033R6YA104KE14D" "FP-GRM033R6YA104KE14D_0201 (0603 Metric)-IPC_C" 5197.1,3791.56 r90 bottom locked
C10 "GRM033R6YA104KE14D" "FP-GRM033R6YA104KE14D_0201 (0603 Metric)-IPC_C" 5162.69,3875.17 r90 bottom
C11 "CL03A105MO3NRNH" FP-CL03A105MO3NRNH_0201-IPC_C 5172.1,3791.41 r270 bottom
C12 "GRM033R6YA104KE14D" "FP-GRM033R6YA104KE14D_0201 (0603 Metric)-IPC_C" 5580.92,3737.11 r0 bottom
C13 "GRM033R6YA104KE14D" "FP-GRM033R6YA104KE14D_0201 (0603 Metric)-IPC_C" 5242.93,4010.48 r0 bottom
C14 "GRM0335C1H4R7BA01D" 0201_033L 3719.34,4001.36 r90 top
C15 "CL03A105MO3NRNH" FP-CL03A105MO3NRNH_0201-IPC_C 4785.89,4123.62 r270 top
C16 "CL03A105MO3NRNH" FP-CL03A105MO3NRNH_0201-IPC_C 4755.82,4123.62 r270 top
C17 "GRM0335C1H8R0BA01D" "FP-GRM0335C1H8R0BA01D_0201 (0603 metric)-IPC_C" 6550.62,4212.94 r90 top
C18 "GRM0335C1H8R0BA01D" "FP-GRM0335C1H8R0BA01D_0201 (0603 metric)-IPC_C" 6550.62,4166.75 r270 top
C19 "250R05L120JV4T" FP-250R05L120JV4T_0201-IPC_C 6277.6,4370.87 r270 top
C20 "250R05L120JV4T" FP-250R05L120JV4T_0201-IPC_C 6277.6,4324.98 r90 top
C21 "CL05C120JB5NNNC" 0402L 6540.73,4344.09 r270 top
C22 "GCM1555C1H1R0CA16D" 0402L 6468.51,4395.47 r270 top
C23 "GCM1555C1H1R0CA16D" 0402L 6395.4,4324.42 r180 top
C24 "CL03A105MO3NRNH" FP-CL03A105MO3NRNH_0201-IPC_C 6142.33,4003.46 r180 top
C25 "GRM033R6YA104KE14D" "FP-GRM033R6YA104KE14D_0201 (0603 Metric)-IPC_C" 6156.95,4250.28 r180 top
C26 "GRM033R6YA104KE14D" "FP-GRM033R6YA104KE14D_0201 (0603 Metric)-IPC_C" 6142.18,4042.21 r180 top
C27 "GRM033R6YA104KE14D" "FP-GRM033R6YA104KE14D_0201 (0603 Metric)-IPC_C" 6559.18,4128.46 r0 top
C28 "CL05A226MQ5N6J8" FP-CL05A226MQ5N6J8_0402-IPC_C 6495.93,3931.35 r270 top
C29 "CL05A226MQ5N6J8" FP-CL05A226MQ5N6J8_0402-IPC_C 6470.18,4142.46 r180 bottom
C30 "LMK063BJ224MP-F" 0201_033L 3107,4029 r180 top
C31 "TMK063CG391JT-F" "FP-TMK063CG391JT-F_0201 (0603 Metric)-IPC_C" 2861.78,4197.4 r270 top
C32 "TMK063CG391JT-F" "FP-TMK063CG391JT-F_0201 (0603 Metric)-IPC_C" 2862.17,4075.45 r90 top
C33 "TMK063CG391JT-F" "FP-TMK063CG391JT-F_0201 (0603 Metric)-IPC_C" 3352.15,4197.4 r270 top
C34 "TMK063CG391JT-F" "FP-TMK063CG391JT-F_0201 (0603 Metric)-IPC_C" 3352.48,4074.03 r90 top
C35 "GRM033R6YA104KE14D" "FP-GRM033R6YA104KE14D_0201 (0603 Metric)-IPC_C" 6471.35,4181.25 r180 bottom
C36 "GRM033R6YA104KE14D" "FP-GRM033R6YA104KE14D_0201 (0603 Metric)-IPC_C" 6518.25,4219.38 r0 top
C37 "GRM033R6YA104KE14D" "FP-GRM033R6YA104KE14D_0201 (0603 Metric)-IPC_C" 6287.19,4411.08 r180 top
C38 "250R05L120JV4T" FP-250R05L120JV4T_0201-IPC_C 5245.41,3795.56 r180 bottom
C39 "250R05L120JV4T" FP-250R05L120JV4T_0201-IPC_C 5291.16,3795.56 r0 bottom
C40 "GRM033R6YA104KE14D" "FP-GRM033R6YA104KE14D_0201 (0603 Metric)-IPC_C" 4961.7,3946.07 r0 top
C41 "GCM1555C1H1R0CA16D" 0402L 6487.09,4570.15 r270 top
C42 "CL05A106MP5NUNC" 0402_070 6821.81,4040 r90 top
C43 "GRM033R6YA104KE14D" "FP-GRM033R6YA104KE14D_0201 (0603 Metric)-IPC_C" 5891.78,4292.07 r0 top
C44 "CGA4J1X7T0J226M125AC" FP-CGA4J1X7T0J226M125AC_0805-MFG 2816.19,4201.22 r270 top
C45 "CGA4J1X7T0J226M125AC" FP-CGA4J1X7T0J226M125AC_0805-MFG 2751.54,3937.35 r270 top
C46 "CGA4J1X7T0J226M125AC" FP-CGA4J1X7T0J226M125AC_0805-MFG 3394.08,4214.97 r270 top
C47 "CGA4J1X7T0J226M125AC" FP-CGA4J1X7T0J226M125AC_0805-MFG 3311.68,3920.88 r270 top
C50 "CL05A106MP5NUNC" 0402_070 2981.75,4173.11 r270 top
C51 "CL05A106MP5NUNC" 0402_070 2981.75,4110.11 r90 top
C52 "CL05A106MP5NUNC" 0402_070 3232.25,4110.11 r90 top
C53 "CL05A106MP5NUNC" 0402_070 3232.25,4173.11 r270 top
C55 "CL05A106MP5NUNC" 0402_070 4115.16,4356.5 r90 bottom
C56 "LMK063BJ224MP-F" 0201_033L 4166.37,4378.24 r0 bottom
C57 "LMK063BJ224MP-F" 0201_033L 4168.42,4409.4 r0 bottom
C58 "LMK063BJ224MP-F" 0201_033L 4125.06,4410.16 r180 bottom
C59 "CL05A106MP5NUNC" 0402_070 4128.3,3985.94 r0 bottom
C60 "LMK063BJ224MP-F" 0201_033L 4378.33,3871.66 r270 top
C61 "LMK063BJ224MP-F" 0201_033L 4270.98,4185.3 r180 bottom
C62 "CL05A106MP5NUNC" 0402_070 3907,4128 r0 bottom
C63 "LMK063BJ224MP-F" 0201_033L 3737.19,4226.49 r90 top
C64 "LMK063BJ224MP-F" 0201_033L 3907,4159 r0 bottom
C65 "CL05A106MP5NUNC" 0402_070 3911,4188 r0 bottom
C66 "LMK063BJ224MP-F" 0201_033L 3908.02,4218 r0 bottom
C67 "LMK063BJ224MP-F" 0201_033L 3848,4327 r90 bottom
C68 "LMK063BJ224MP-F" 0201_033L 3884.37,4409.24 r0 bottom
C69 "GRM033R61C473KE84D" 0201_033L 3734.67,4322.98 r270 top
C70 "CL05A106MP5NUNC" 0402_070 3891,4337 r180 bottom
C71 "GRM0335C1H4R7BA01D" 0201_033L 3722.86,4065.25 r270 top
C72 "GRM033R6YA104KE14D" "FP-GRM033R6YA104KE14D_0201 (0603 Metric)-IPC_C" 4853.37,4217.48 r270 top
C73 "CL05A106MP5NUNC" 0402_070 3897,4303 r180 bottom
C74 "CL03A225MQ3CRNC" 0201L 3945.46,4346.38 r180 bottom
C75 "LMK063BJ224MP-F" 0201_033L 3945.46,4409.24 r180 bottom
C76 "LMK063BJ224MP-F" 0201_033L 3945.46,4377.91 r180 bottom
C78 "CL05A106MP5NUNC" 0402_070 4038.9,4317.13 r180 bottom
C79 "CL03A225MQ3CRNC" 0201L 4071.88,4346.34 r0 bottom
C80 "LMK063BJ224MP-F" 0201_033L 4073.37,4377.75 r0 bottom
C81 "LMK063BJ224MP-F" 0201_033L 4071.88,4409.36 r0 bottom
C82 "CL05A106MP5NUNC" 0402_070 4001.02,4277.32 r0 bottom
C83 "CL03A225MQ3CRNC" 0201L 4008.9,4346.15 r0 bottom
C84 "LMK063BJ224MP-F" 0201_033L 4009.24,4377.83 r0 bottom
C85 "LMK063BJ224MP-F" 0201_033L 4009.24,4409.33 r0 bottom
C86 "GRM033R6YA104KE14D" "FP-GRM033R6YA104KE14D_0201 (0603 Metric)-IPC_C" 6422.23,3935.32 r0 bottom
C87 "LMK063BJ224MP-F" 0201_033L 4019.98,3861.38 r0 bottom
C88 "LMK063BJ224MP-F" 0201_033L 4394.91,4124.76 r0 top
C89 "CGB2A1X6S0J105K033BC" 0402L 3717.5,4135.45 r180 top
C90 "CGB2A1X6S0J105K033BC" 0402L 3717.37,4182.85 r180 top
C91 "GRM033R6YA104KE14D" "FP-GRM033R6YA104KE14D_0201 (0603 Metric)-IPC_C" 4292.99,4035.17 r180 bottom
C92 "GRM033R6YA104KE14D" "FP-GRM033R6YA104KE14D_0201 (0603 Metric)-IPC_C" 4065.74,3883.1 r90 bottom
C93 "CL05C120JB5NNNC" 0402L 6717.79,4589.83 r180 top
C94 "LMK063BJ224MP-F" 0201_033L 4293.19,3964.68 r180 bottom
C95 "LMK063BJ224MP-F" 0201_033L 3922.37,3891.76 r90 bottom
C96 "LMK063BJ224MP-F" 0201_033L 4388.37,4235.76 r90 top
C97 "LMK063BJ224MP-F" 0201_033L 3779.79,4050.2 r90 bottom
C98 "LMK063BJ224MP-F" 0201_033L 4388.37,4297.76 r270 top
C99 "GJM1555C1H1R8BB01D" 0402L 6840.79,4589.83 r180 top
C100 "CL03A105MO3NRNH" FP-CL03A105MO3NRNH_0201-IPC_C 3741.24,3861.69 r0 bottom
C101 "GRM033R6YA104KE14D" "FP-GRM033R6YA104KE14D_0201 (0603 Metric)-IPC_C" 3741,3881.17 r0 bottom
C102 "CL03A225MQ3CRNC" 0201L 4393.22,4090.26 r0 top
C103 "CL03A225MQ3CRNC" 0201L 4291.98,4058.8 r180 bottom
C104 "GJM1555C1H1R8BB01D" 0402L 6962.22,4570.15 r270 top
C105 "GRM033R6YA104KE14D" "FP-GRM033R6YA104KE14D_0201 (0603 Metric)-IPC_C" 6003.64,4429.32 r90 top
C106 "GRM155R71H472KA01D" 0402L 6042.33,4472.32 r90 top
C107 "GRM033R6YA104KE14D" "FP-GRM033R6YA104KE14D_0201 (0603 Metric)-IPC_C" 6735.03,4433.22 r90 top
C108 "GRM033R6YA104KE14D" "FP-GRM033R6YA104KE14D_0201 (0603 Metric)-IPC_C" 6709.78,3866.01 r270 top
C109 "GRM033R6YA104KE14D" "FP-GRM033R6YA104KE14D_0201 (0603 Metric)-IPC_C" 6877.41,3768.9 r0 top
C110 "GRM155R71H472KA01D" 0402L 6951.81,3773.61 r90 top
C111 "CGA4J1X7T0J226M125AC" FP-CGA4J1X7T0J226M125AC_0805-MFG 3322.6,4362.32 r90 top
C112 "CGA4J1X7T0J226M125AC" FP-CGA4J1X7T0J226M125AC_0805-MFG 2818.89,4074.44 r90 top
C113 "CGA4J1X7T0J226M125AC" FP-CGA4J1X7T0J226M125AC_0805-MFG 3244.4,4362.32 r90 top
C114 "GRM033R6YA104KE14D" "FP-GRM033R6YA104KE14D_0201 (0603 Metric)-IPC_C" 6174.57,3747.34 r180 bottom
C115 "CL03A105MO3NRNH" FP-CL03A105MO3NRNH_0201-IPC_C 5764.72,3872.2 r0 top
C116 "CL03A105MO3NRNH" FP-CL03A105MO3NRNH_0201-IPC_C 5764.72,3843.74 r0 top
C117 "GRM033R6YA104KE14D" "FP-GRM033R6YA104KE14D_0201 (0603 Metric)-IPC_C" 5322,4534 r0 bottom
C118 "GRM033R6YA104KE14D" "FP-GRM033R6YA104KE14D_0201 (0603 Metric)-IPC_C" 6272.5,3733.87 r270 bottom
C119 "GRM033R6YA104KE14D" "FP-GRM033R6YA104KE14D_0201 (0603 Metric)-IPC_C" 6308.91,3909.21 r90 bottom
C120 "GRM033R6YA104KE14D" "FP-GRM033R6YA104KE14D_0201 (0603 Metric)-IPC_C" 4784.37,4437.46 r90 top
C121 "CGA4J1X7T0J226M125AC" FP-CGA4J1X7T0J226M125AC_0805-MFG 3396.69,4076.02 r90 top
C122 "CL05A106MP5NUNC" 0402_070 6771.81,4040 r270 top
C123 "GRM033R6YA104KE14D" "FP-GRM033R6YA104KE14D_0201 (0603 Metric)-IPC_C" 5432.91,4016.37 r270 bottom
C124 "GCM21BR71A106KE22L" 0805_HV 3091.88,4372.69 r270 bottom
C125 "CL03A103KA3NNNC" FP-CL03A103KA3NNNC_0201-IPC_C 5270.83,4102.9 r0 bottom locked
C126 "GRM033R6YA104KE14D" "FP-GRM033R6YA104KE14D_0201 (0603 Metric)-IPC_C" 3679.93,4262.91 r0 top
C127 "GRM033R6YA104KE14D" "FP-GRM033R6YA104KE14D_0201 (0603 Metric)-IPC_C" 6653.18,3936.75 r180 bottom
C128 "GRM033R6YA104KE14D" "FP-GRM033R6YA104KE14D_0201 (0603 Metric)-IPC_C" 6643.28,3766.12 r180 bottom
C129 "CL03A105MO3NRNH" FP-CL03A105MO3NRNH_0201-IPC_C 6719.58,3813.74 r270 bottom
C130 "GRM033R6YA104KE14D" "FP-GRM033R6YA104KE14D_0201 (0603 Metric)-IPC_C" 4251.69,4228 r180 bottom
C131 "CGA4J1X7T0J226M125AC" FP-CGA4J1X7T0J226M125AC_0805-MFG 3462.45,4216.65 r270 top
C132 "GCM21BR71A106KE22L" 0805_HV 3541.84,4216.94 r270 top
C133 "CGA4J1X7T0J226M125AC" FP-CGA4J1X7T0J226M125AC_0805-MFG 2979.21,3912.58 r90 top
C134 "GCM21BR71A106KE22L" 0805_HV 2883.61,3922.66 r90 bottom
C135 "CGA4J1X7T0J226M125AC" FP-CGA4J1X7T0J226M125AC_0805-MFG 3466.11,4077.11 r90 top
C136 "GCM21BR71A106KE22L" 0805_HV 3428.48,3894.97 r180 top
C137 "CGA4J1X7T0J226M125AC" FP-CGA4J1X7T0J226M125AC_0805-MFG 3074.32,4359.33 r270 top
C138 "CGA4J1X7T0J226M125AC" FP-CGA4J1X7T0J226M125AC_0805-MFG 3559.23,3925.63 r0 top
C139 "CGA4J1X7T0J226M125AC" FP-CGA4J1X7T0J226M125AC_0805-MFG 2997.27,4360.78 r270 top
C140 "CGA4J1X7T0J226M125AC" FP-CGA4J1X7T0J226M125AC_0805-MFG 3544.88,4403.6 r0 top
C141 "CGA4J1X7T0J226M125AC" FP-CGA4J1X7T0J226M125AC_0805-MFG 2905,3911.44 r90 top
D1 "NSR20F30NXT5G" DSN2_0603 2804.54,4211.99 r270 bottom
D2 "NSR20F30NXT5G" DSN2_0603 4603.84,3756.88 r0 top locked
Designator1 "Comment" MHNP_M2_PANHEAD_PHILLIPS 2684.58,4830.46 r0 top
Designator1_2 "Comment" MHNP_M2_PANHEAD_PHILLIPS 2684.58,3467.85 r0 bottom
Designator2 "BRAKE_WAY_HOLES1X2" BRAKE_WAY_HOLES1X2 3353.11,4495.01 r180 top
Designator2_1 "BRAKE_WAY_HOLES1X2" BRAKE_WAY_HOLES1X2 3353.11,3788.2 r180 bottom
Designator3 "BRAKE_WAY_HOLES1X2" BRAKE_WAY_HOLES1X2 3848.11,4495.01 r180 top
Designator3_1 "BRAKE_WAY_HOLES1X2" BRAKE_WAY_HOLES1X2 3848.11,3788.2 r180 bottom
Designator4 "BRAKE_WAY_HOLES1X2" BRAKE_WAY_HOLES1X2 4723.45,4688.12 r180 top
Designator4_1 "BRAKE_WAY_HOLES1X2" BRAKE_WAY_HOLES1X2 4723.13,3606.99 r180 bottom
Designator5 "BRAKE_WAY_HOLES1X2" BRAKE_WAY_HOLES1X2 6701.12,4687.21 r180 top
Designator5_1 "BRAKE_WAY_HOLES1X2" BRAKE_WAY_HOLES1X2 6700.8,3607.9 r180 bottom
Designator6 "Comment" MHNP_M2_PANHEAD_PHILLIPS 7012.34,4830.46 r0 top
Designator7 "Comment" MHNP_M2_PANHEAD_PHILLIPS 7012.03,3464.65 r0 top
Designator10 "BRAKE_WAY_HOLES1X2" BRAKE_WAY_HOLES1X2 2796.89,4495.01 r180 top
Designator11 "BRAKE_WAY_HOLES1X2" BRAKE_WAY_HOLES1X2 2796.89,3788.2 r180 bottom
Designator22_1 "Comment" MHNP_2-5 6425,3754.84 r0 bottom
Designator23 "Comment" MHNP_2-5 5014.62,3754.06 r0 bottom
FID2 "Fiducial" FIDUCIAL6.4-20#1 2837.27,4580 r0 top
FID2_1 "Fiducial" FIDUCIAL6.4-20#2 2834.58,4820.46 r0 top (schematic designator FID2)
FID2_1_1 "Fiducial" FIDUCIAL6.4-20#2 2834.58,3477.85 r0 bottom (schematic designator FID2)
